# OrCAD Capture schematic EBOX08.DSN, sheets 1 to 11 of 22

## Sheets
1 22 A10-IO: size C
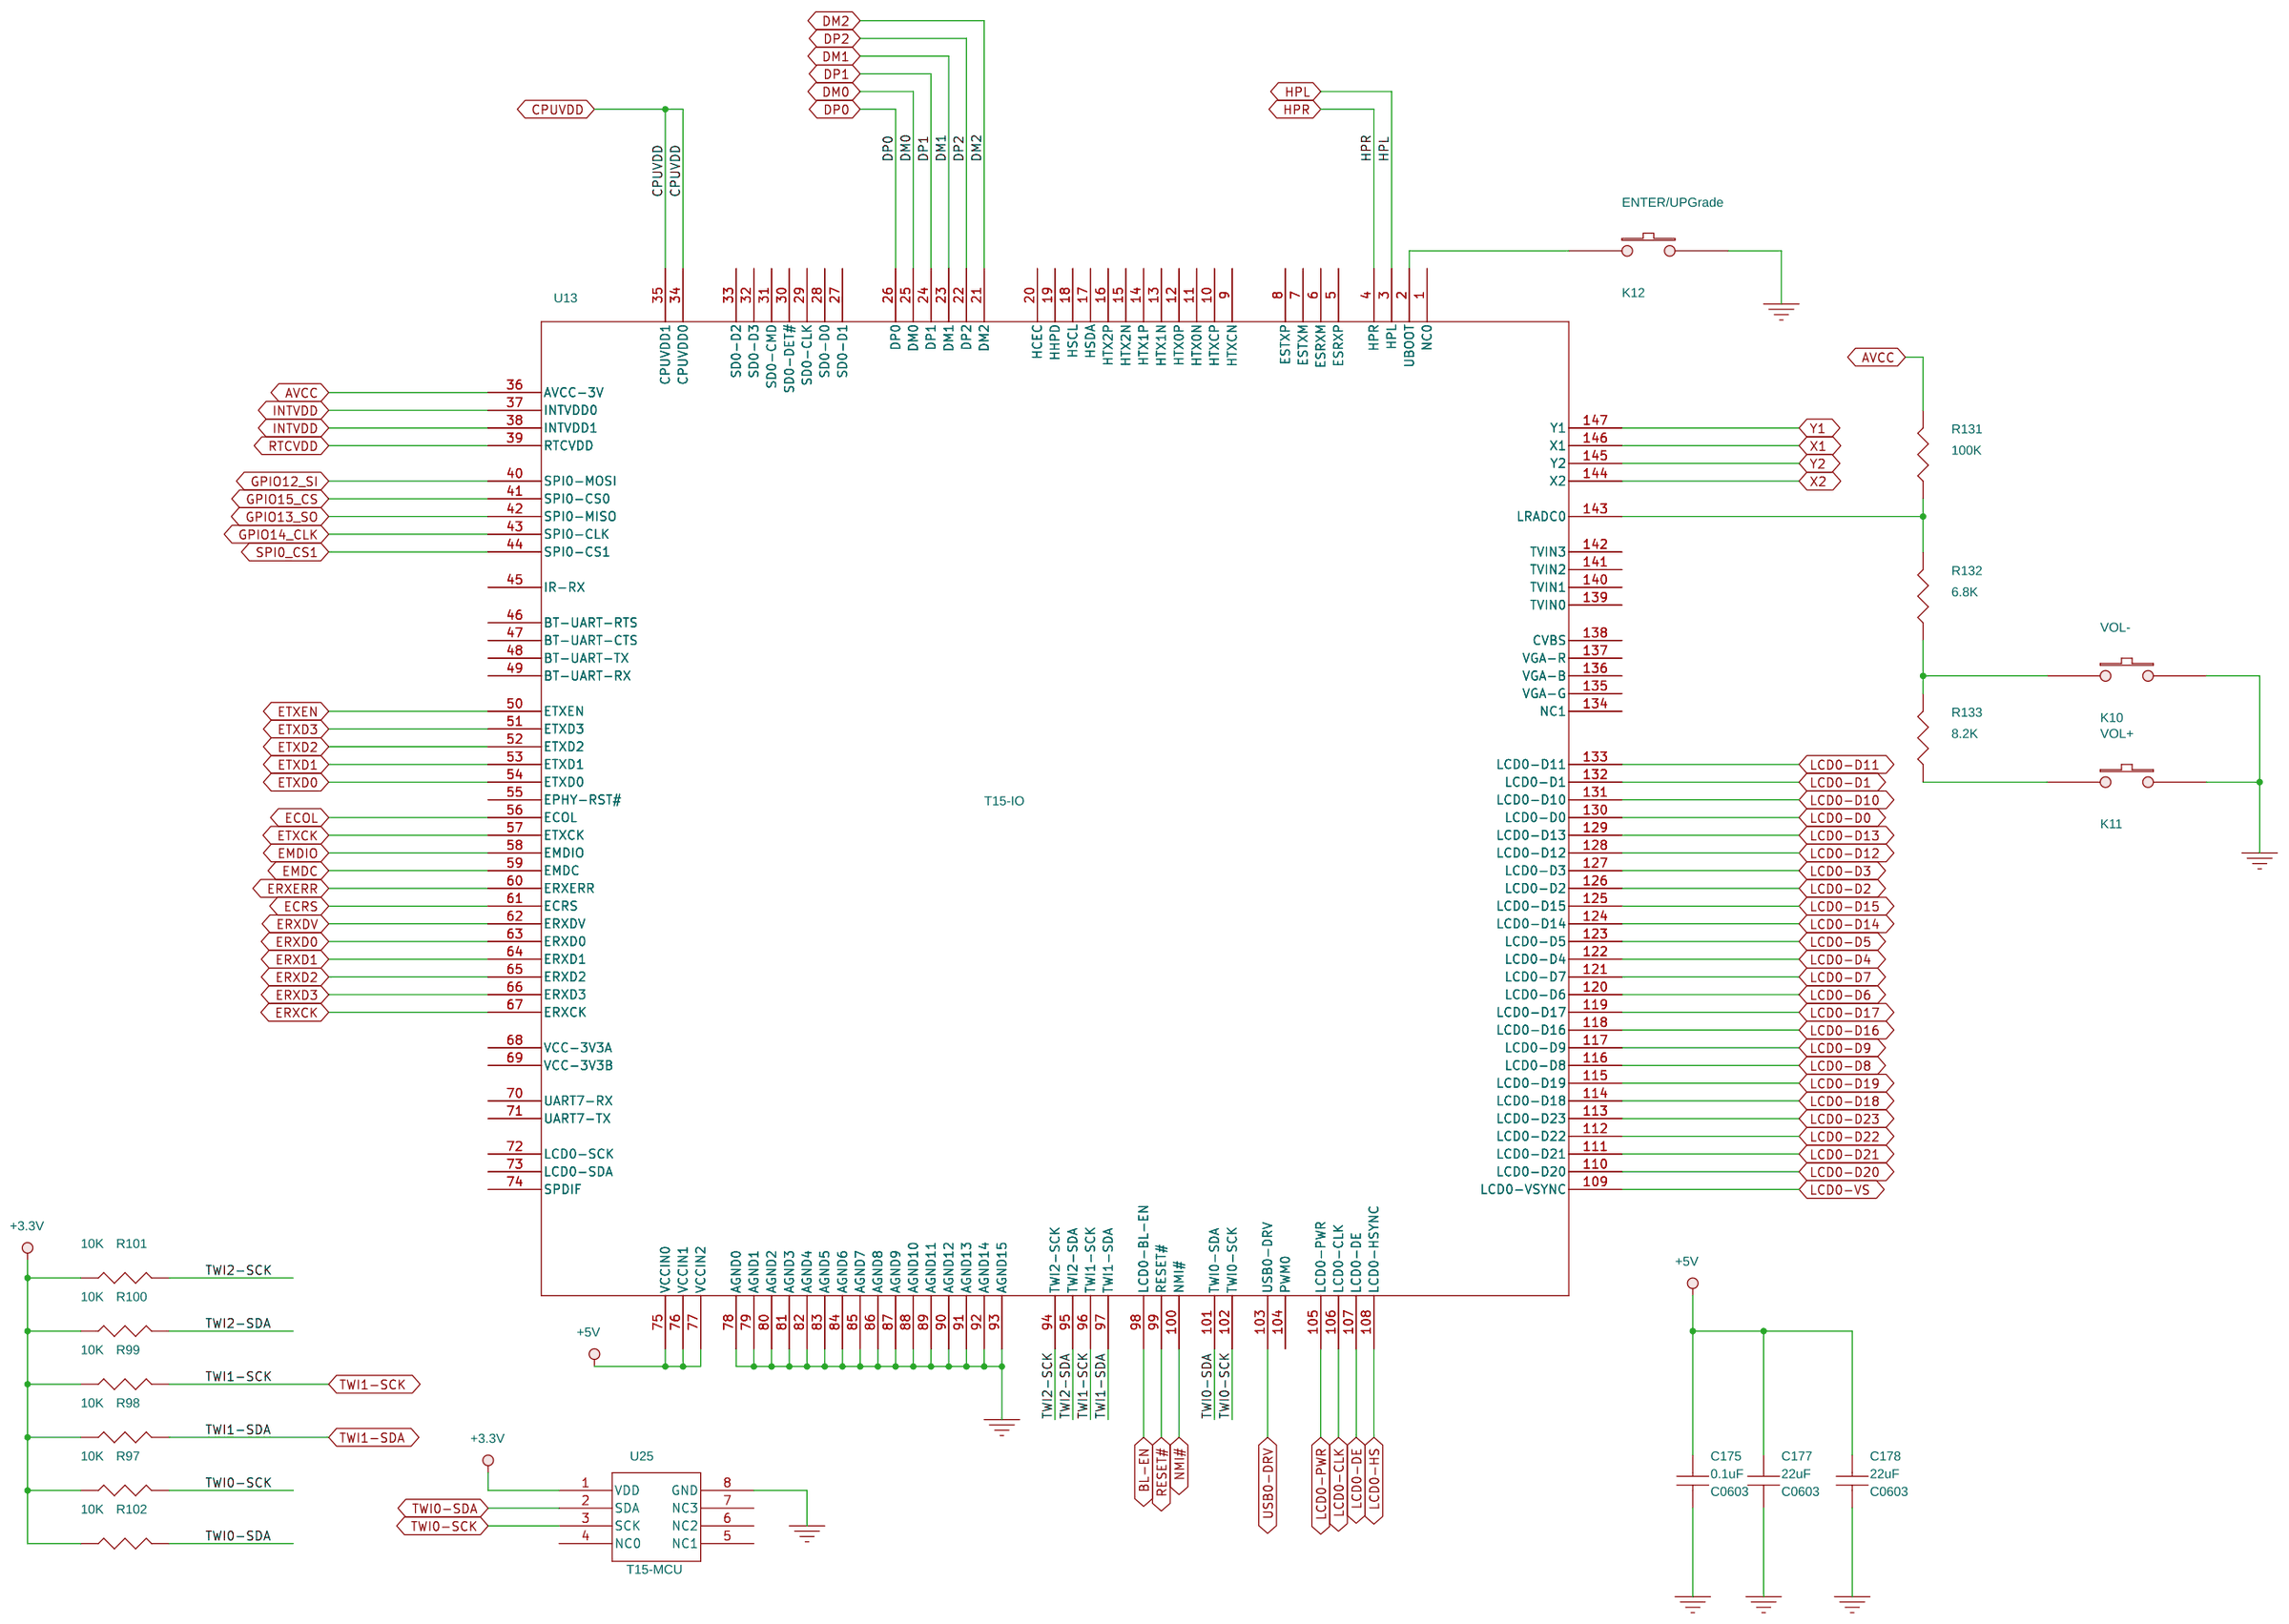
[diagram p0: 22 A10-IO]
2 01 BLOCK
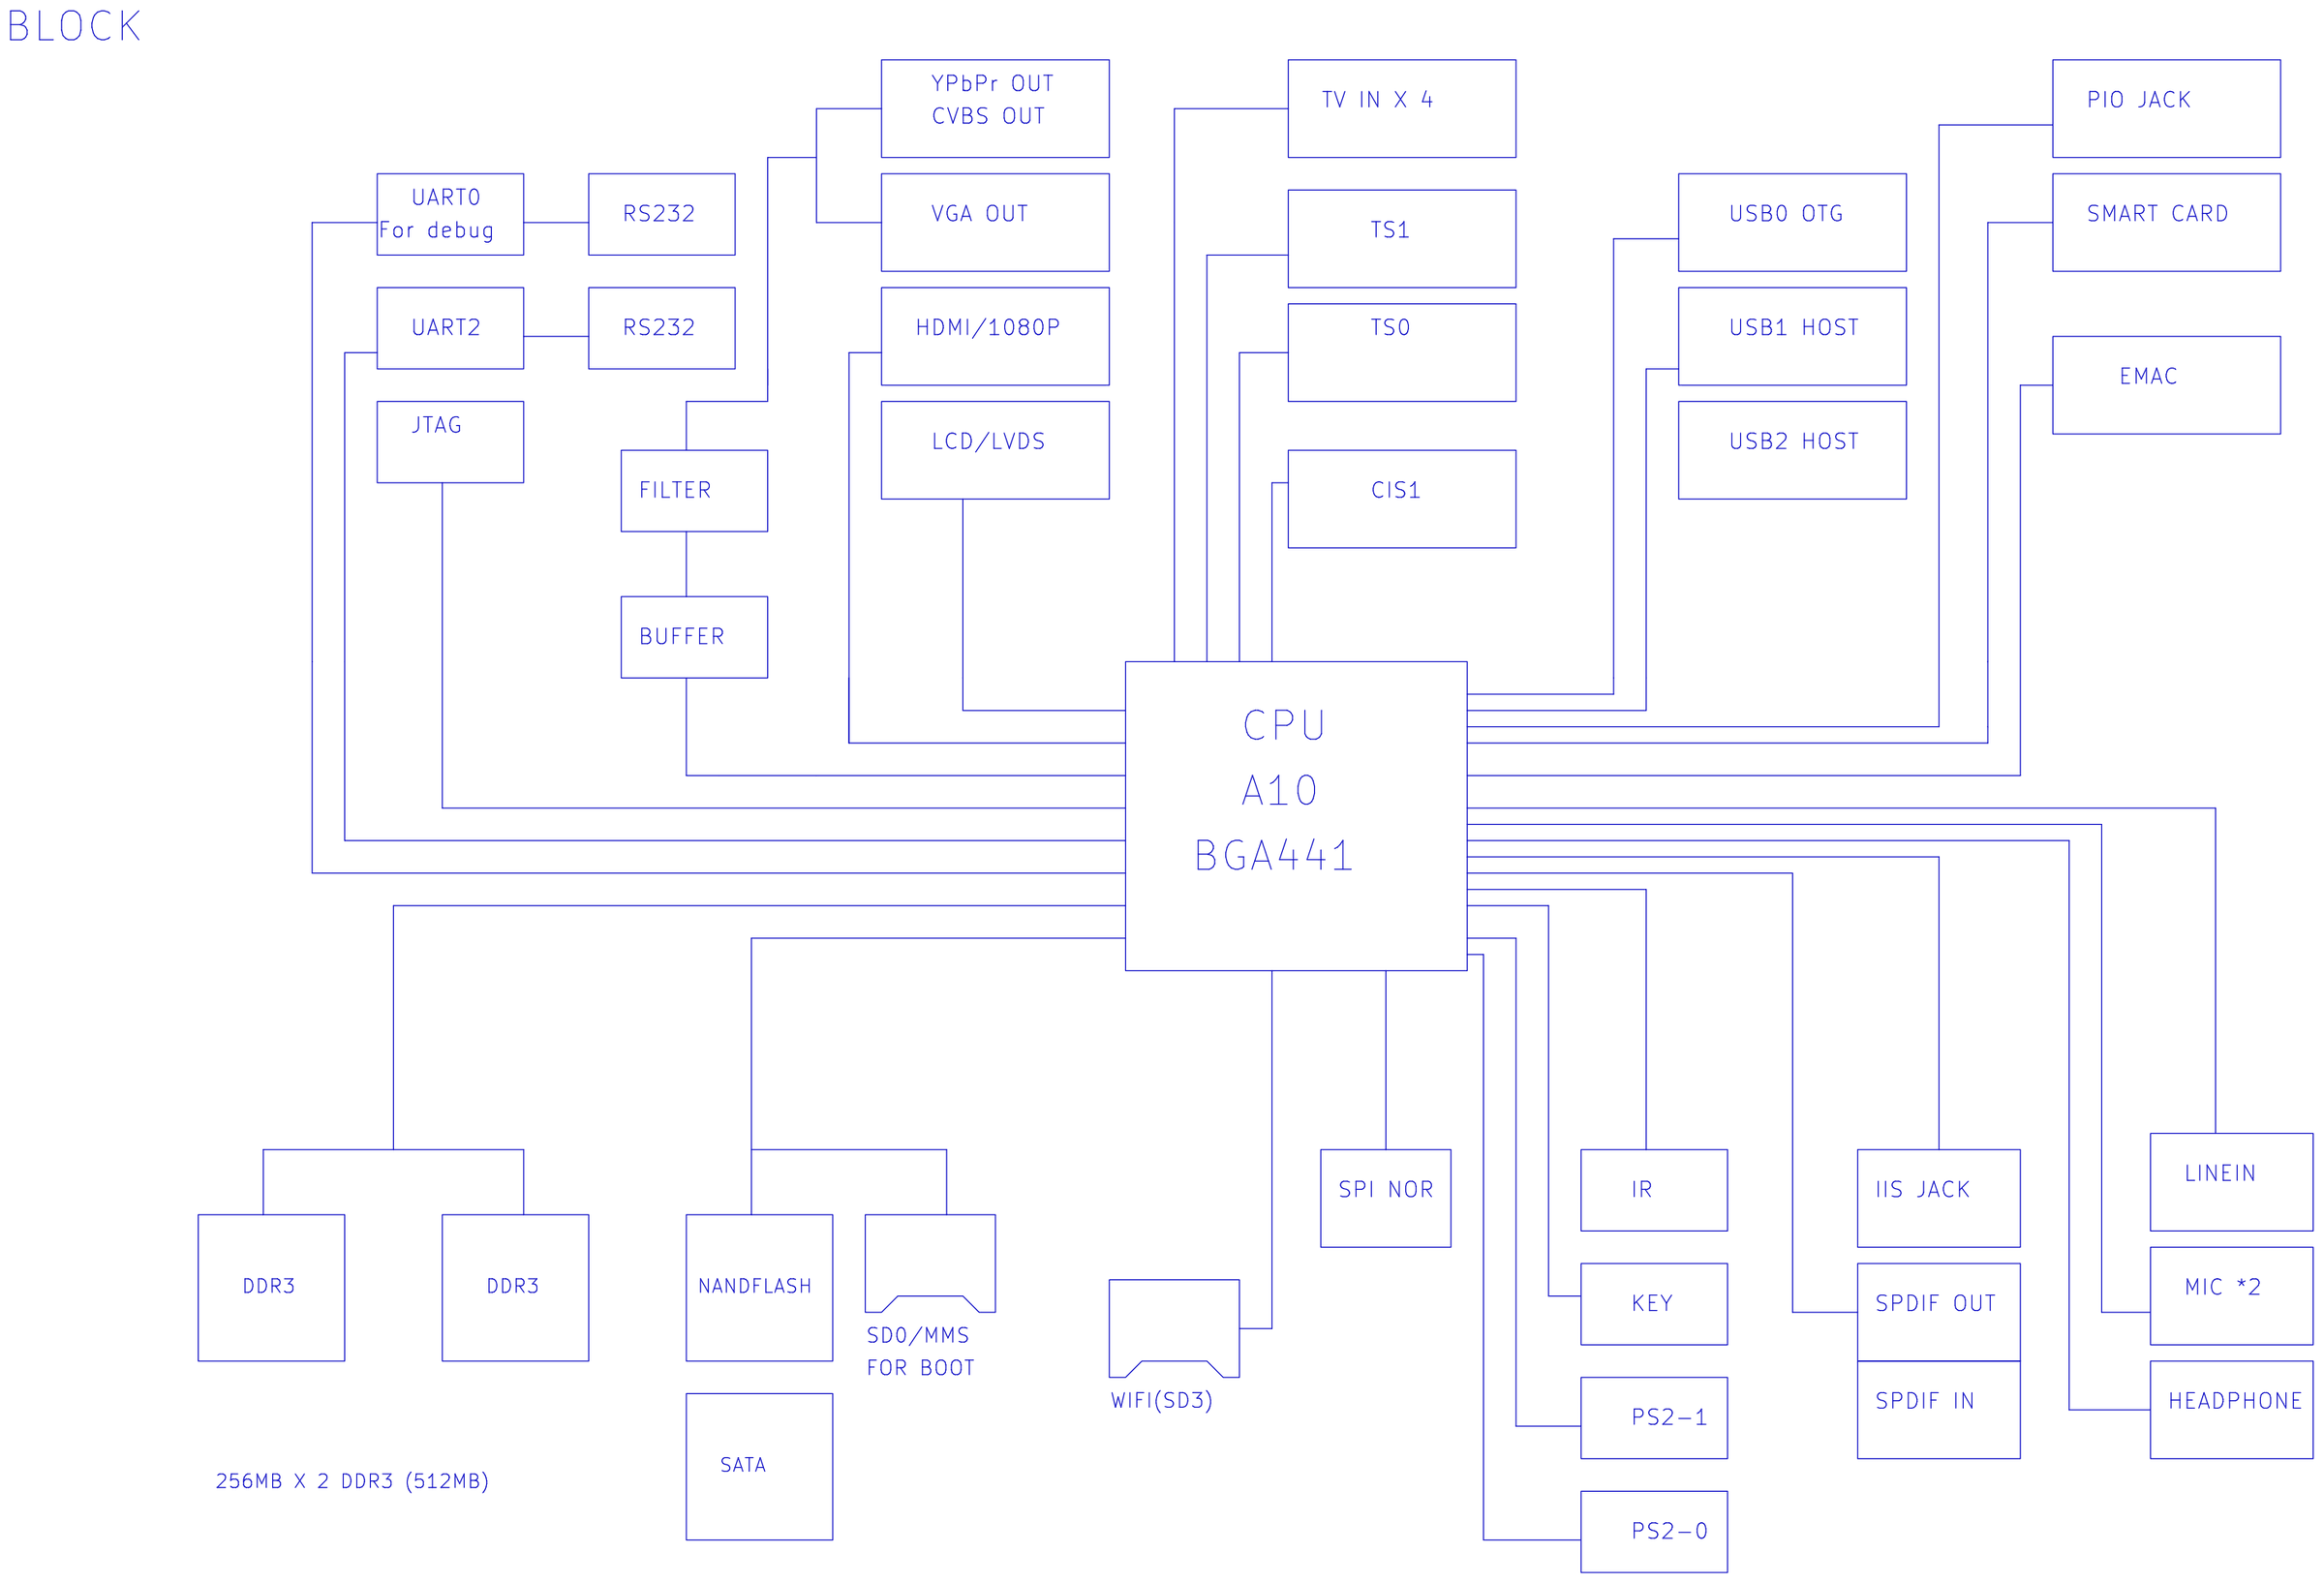
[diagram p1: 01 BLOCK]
3 02 PIO ASSIGNMENT
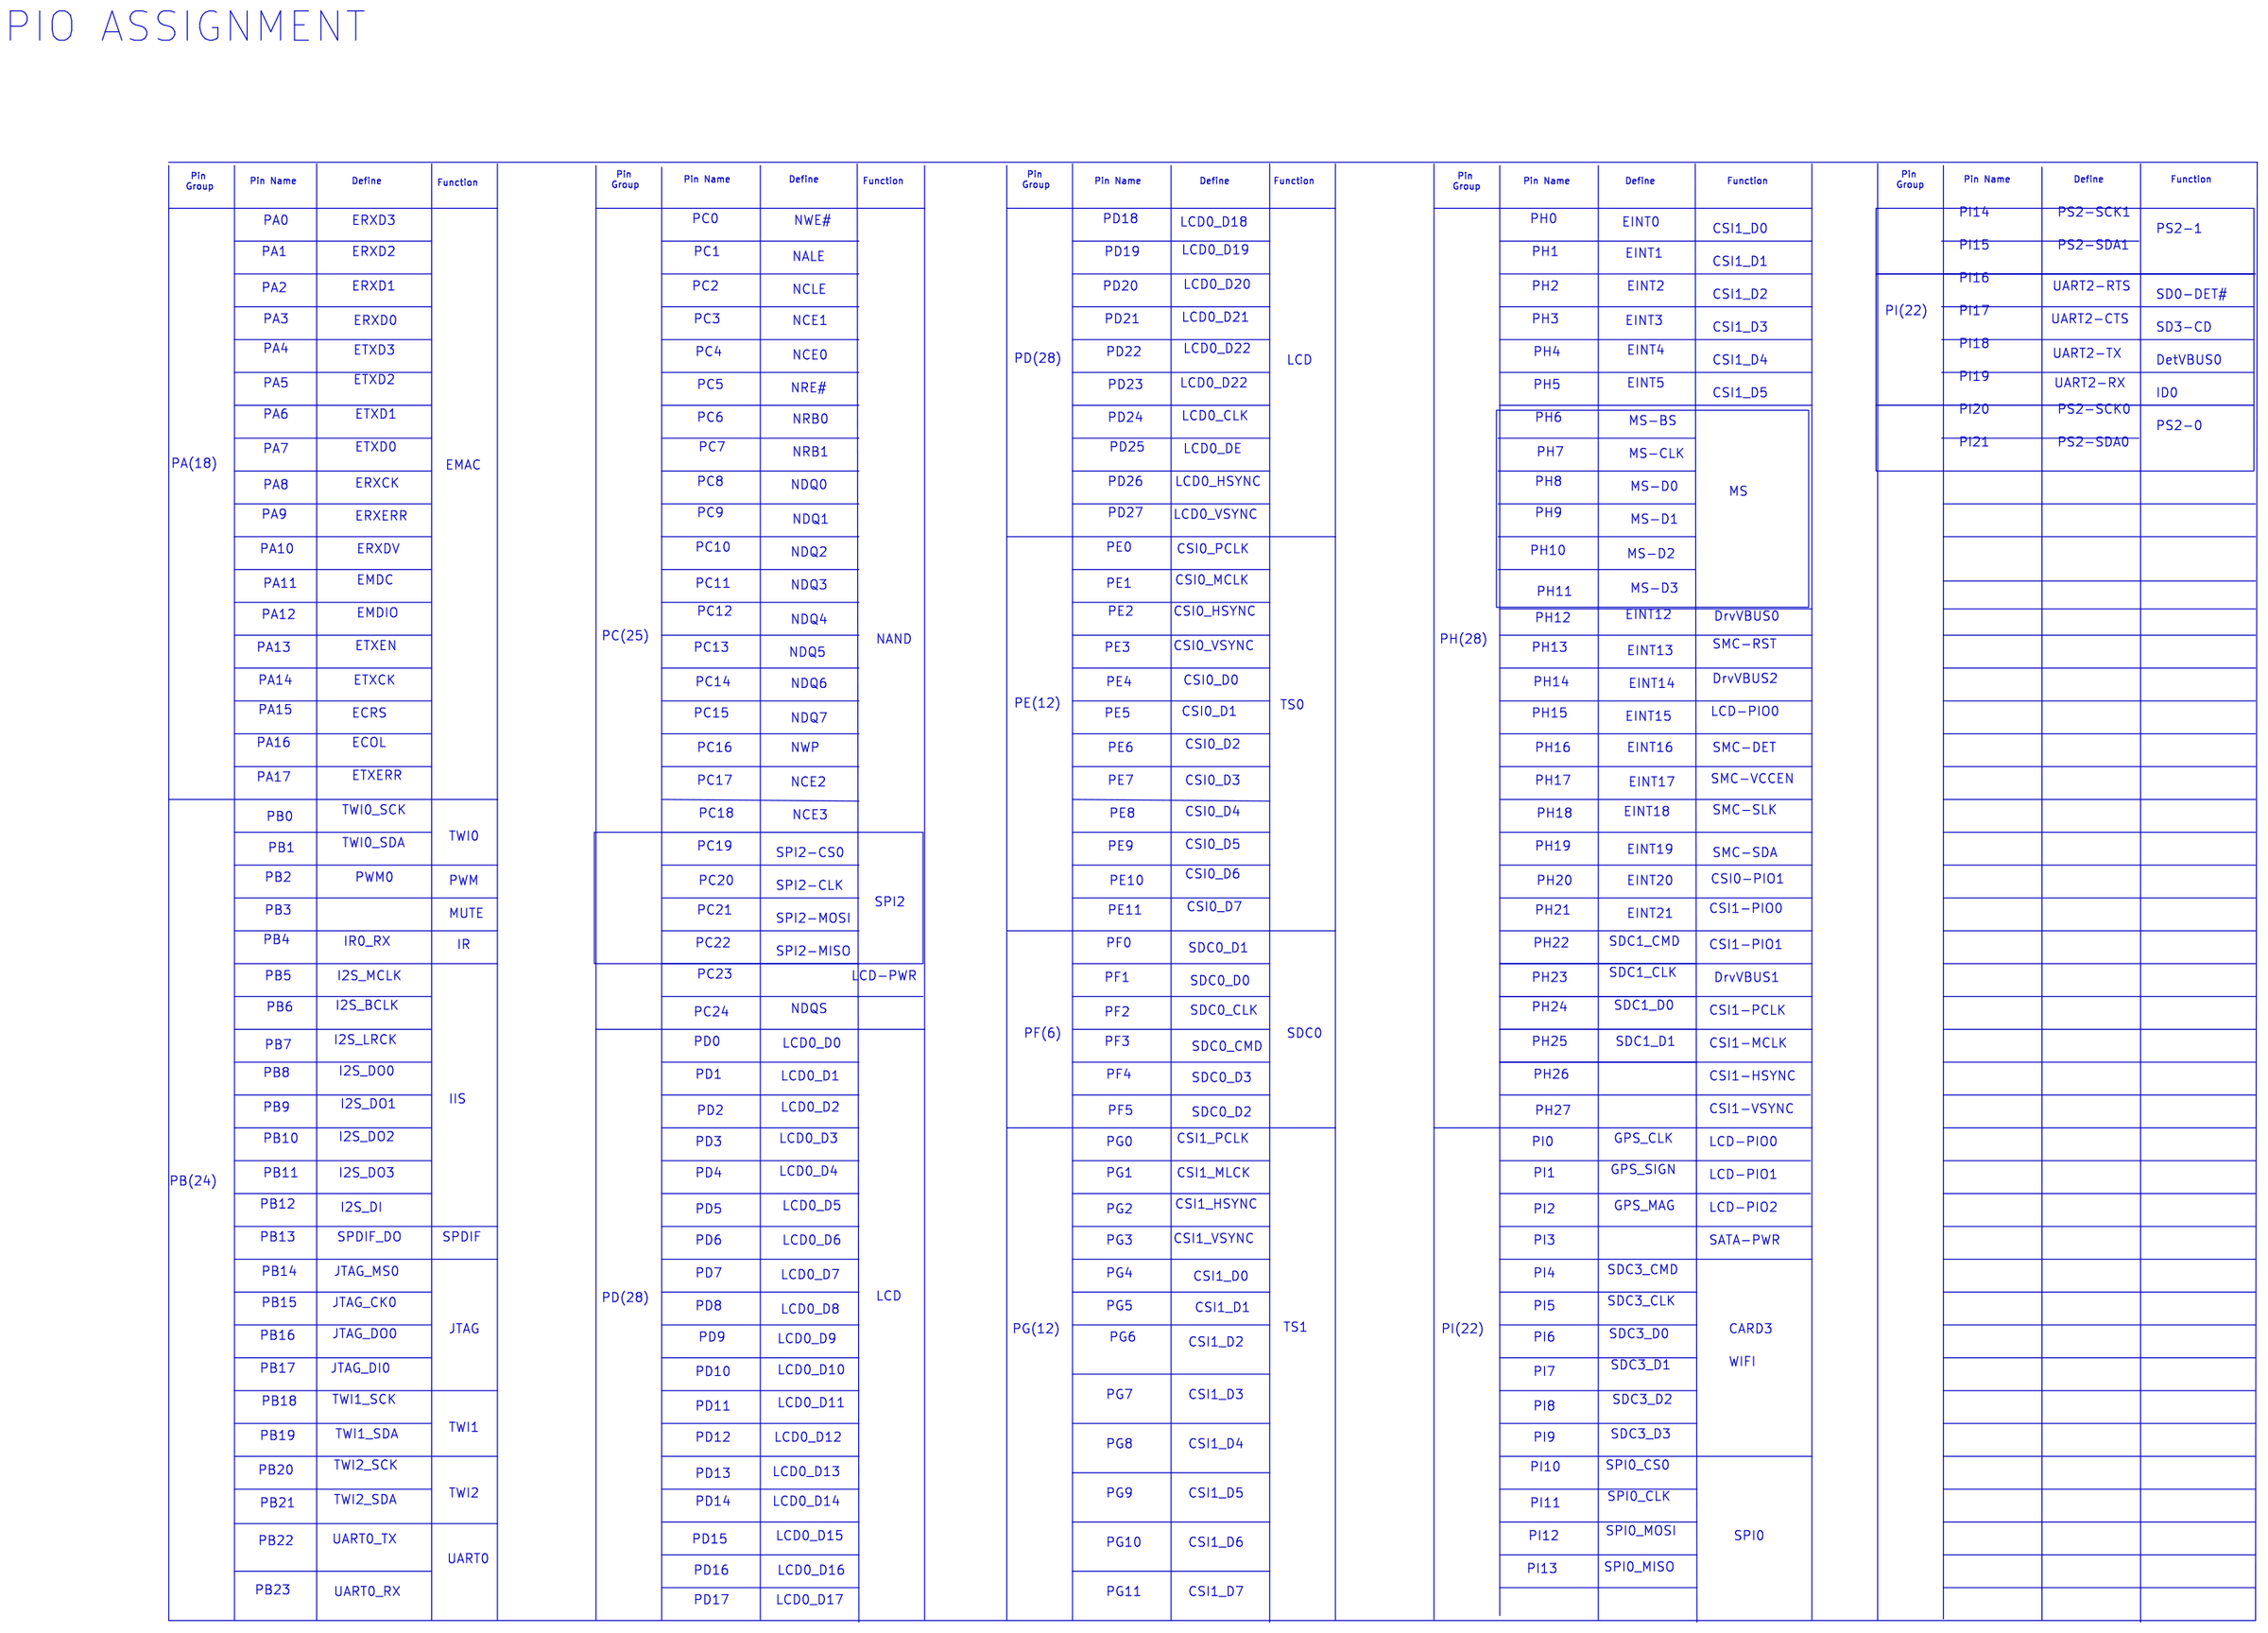
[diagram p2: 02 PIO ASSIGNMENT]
4 03 POWER TREE: title: A10-EVB-TVD-V10; rev: 1.0; note: POWER TREE
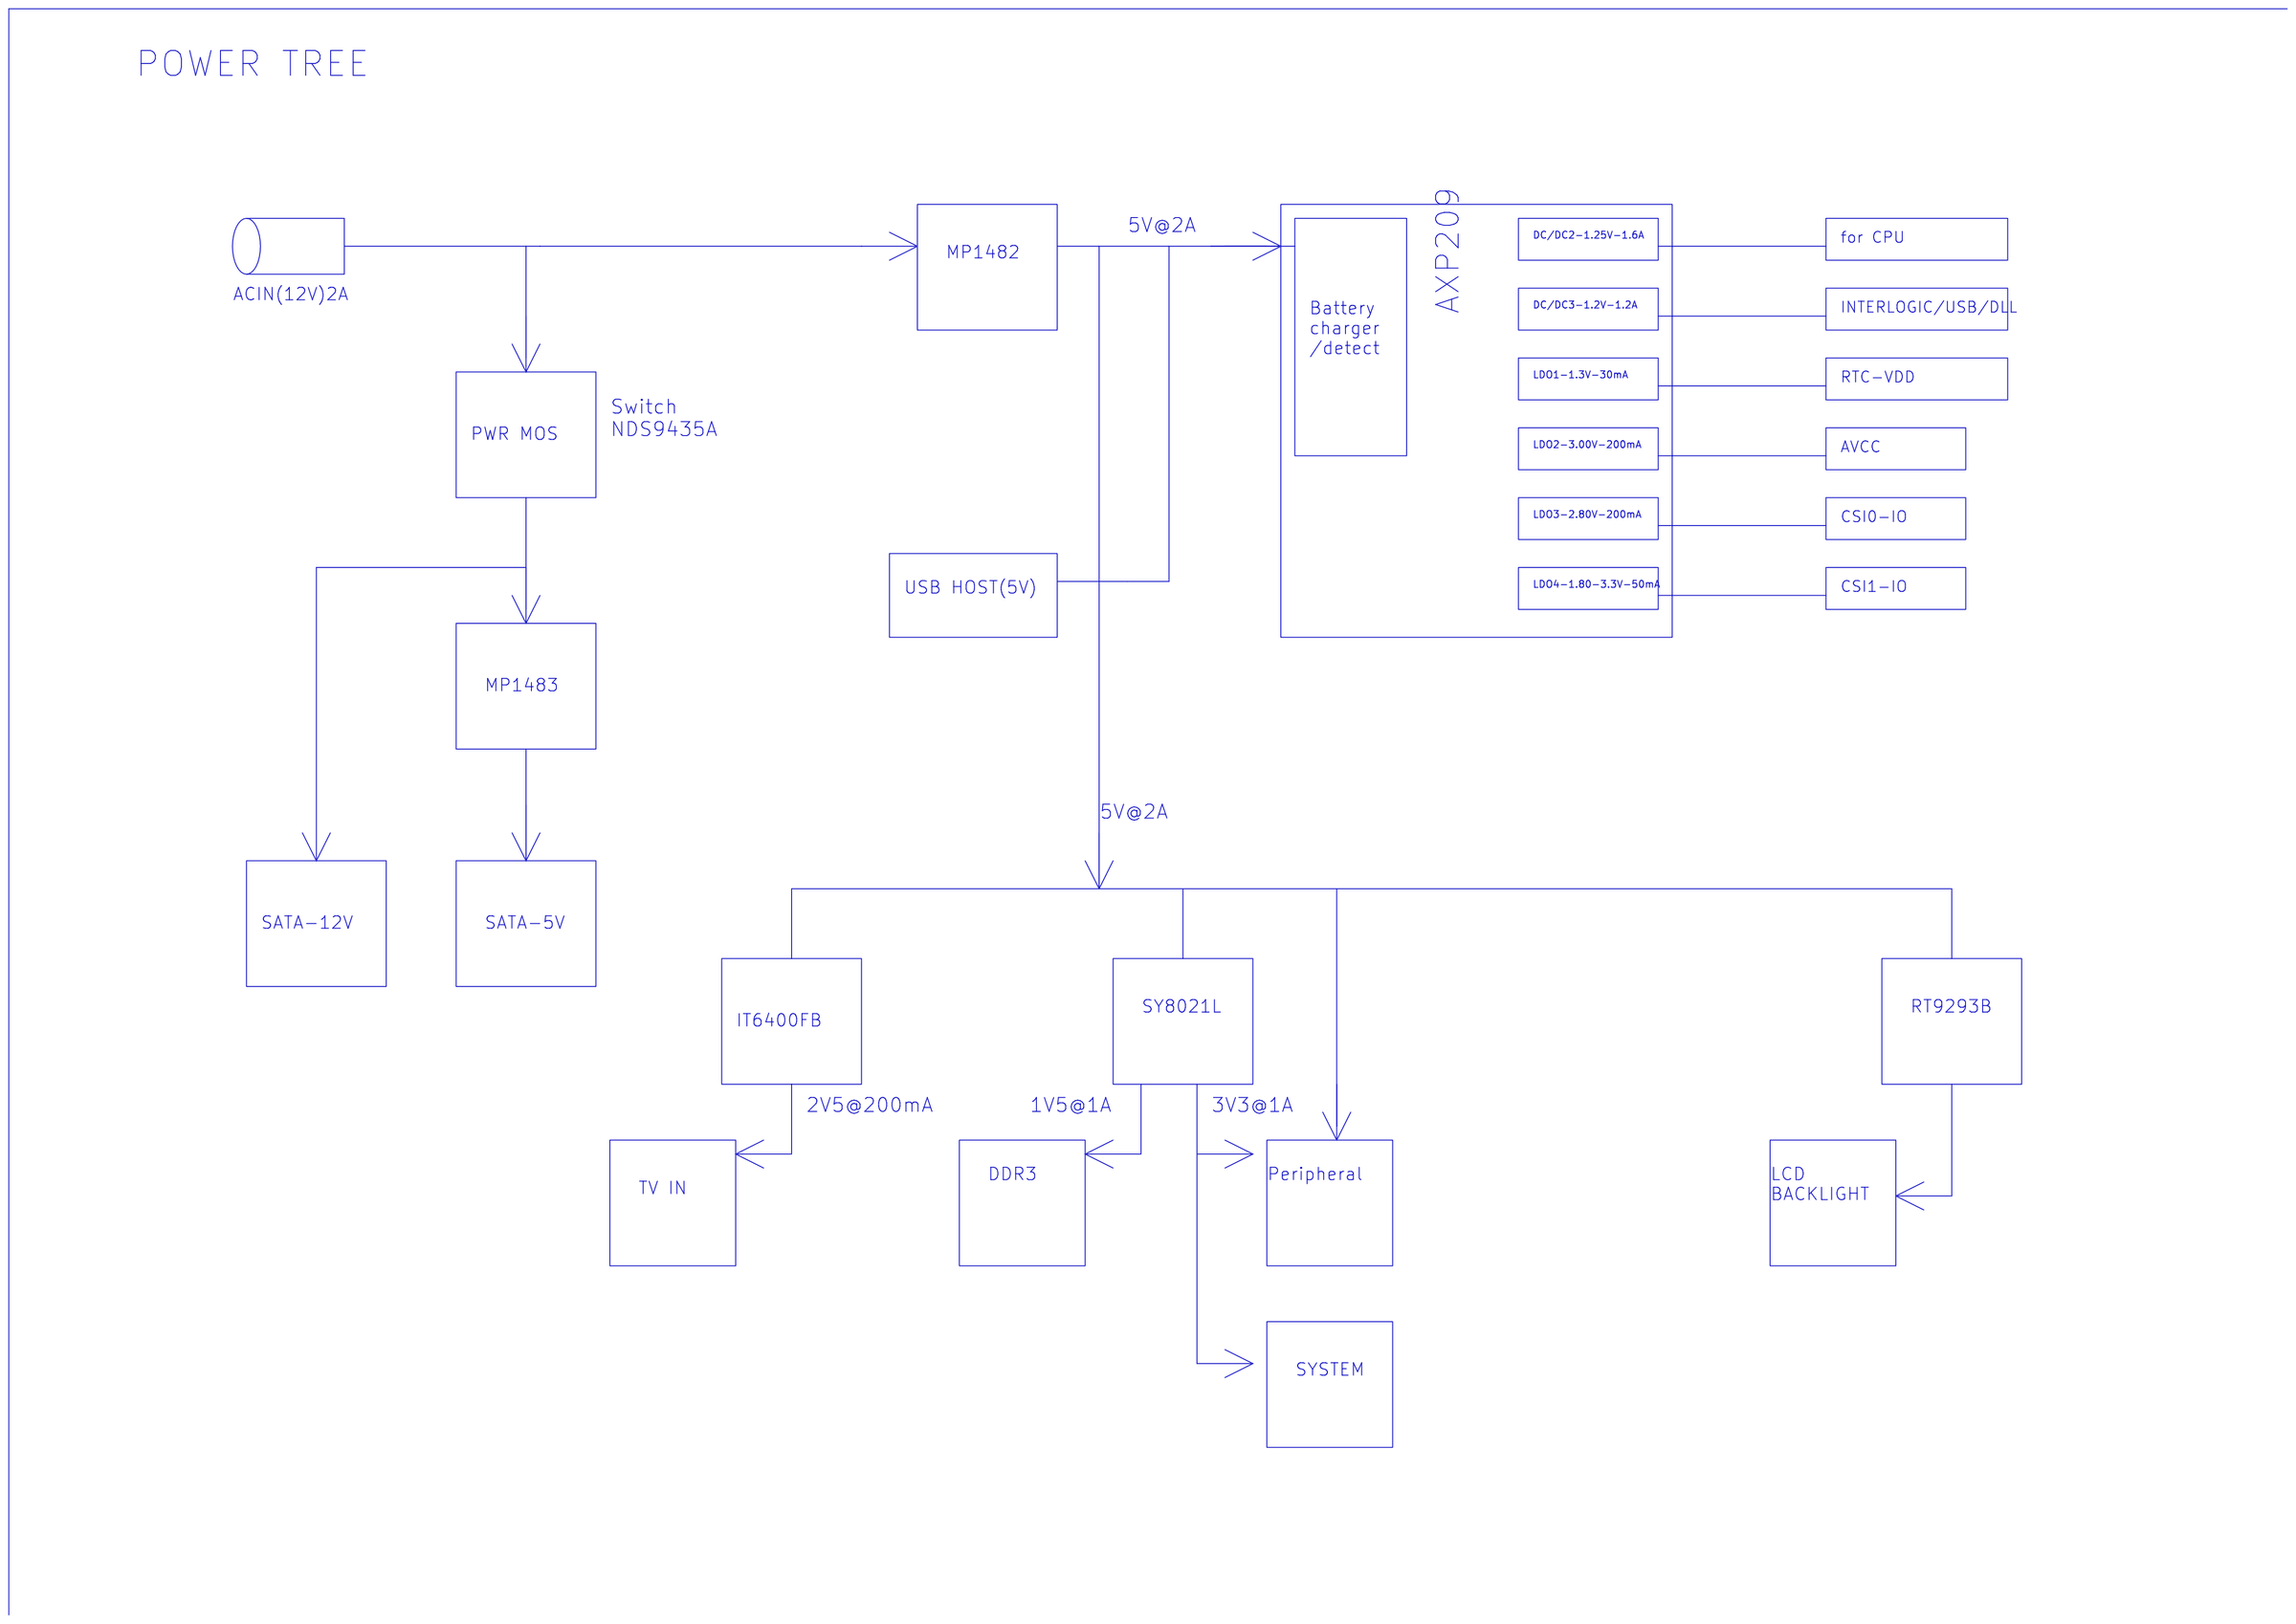
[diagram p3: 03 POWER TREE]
5 04 CPU1: size A3; title: A10-EVB-TVD-V10; rev: 1.0; note: CPU1
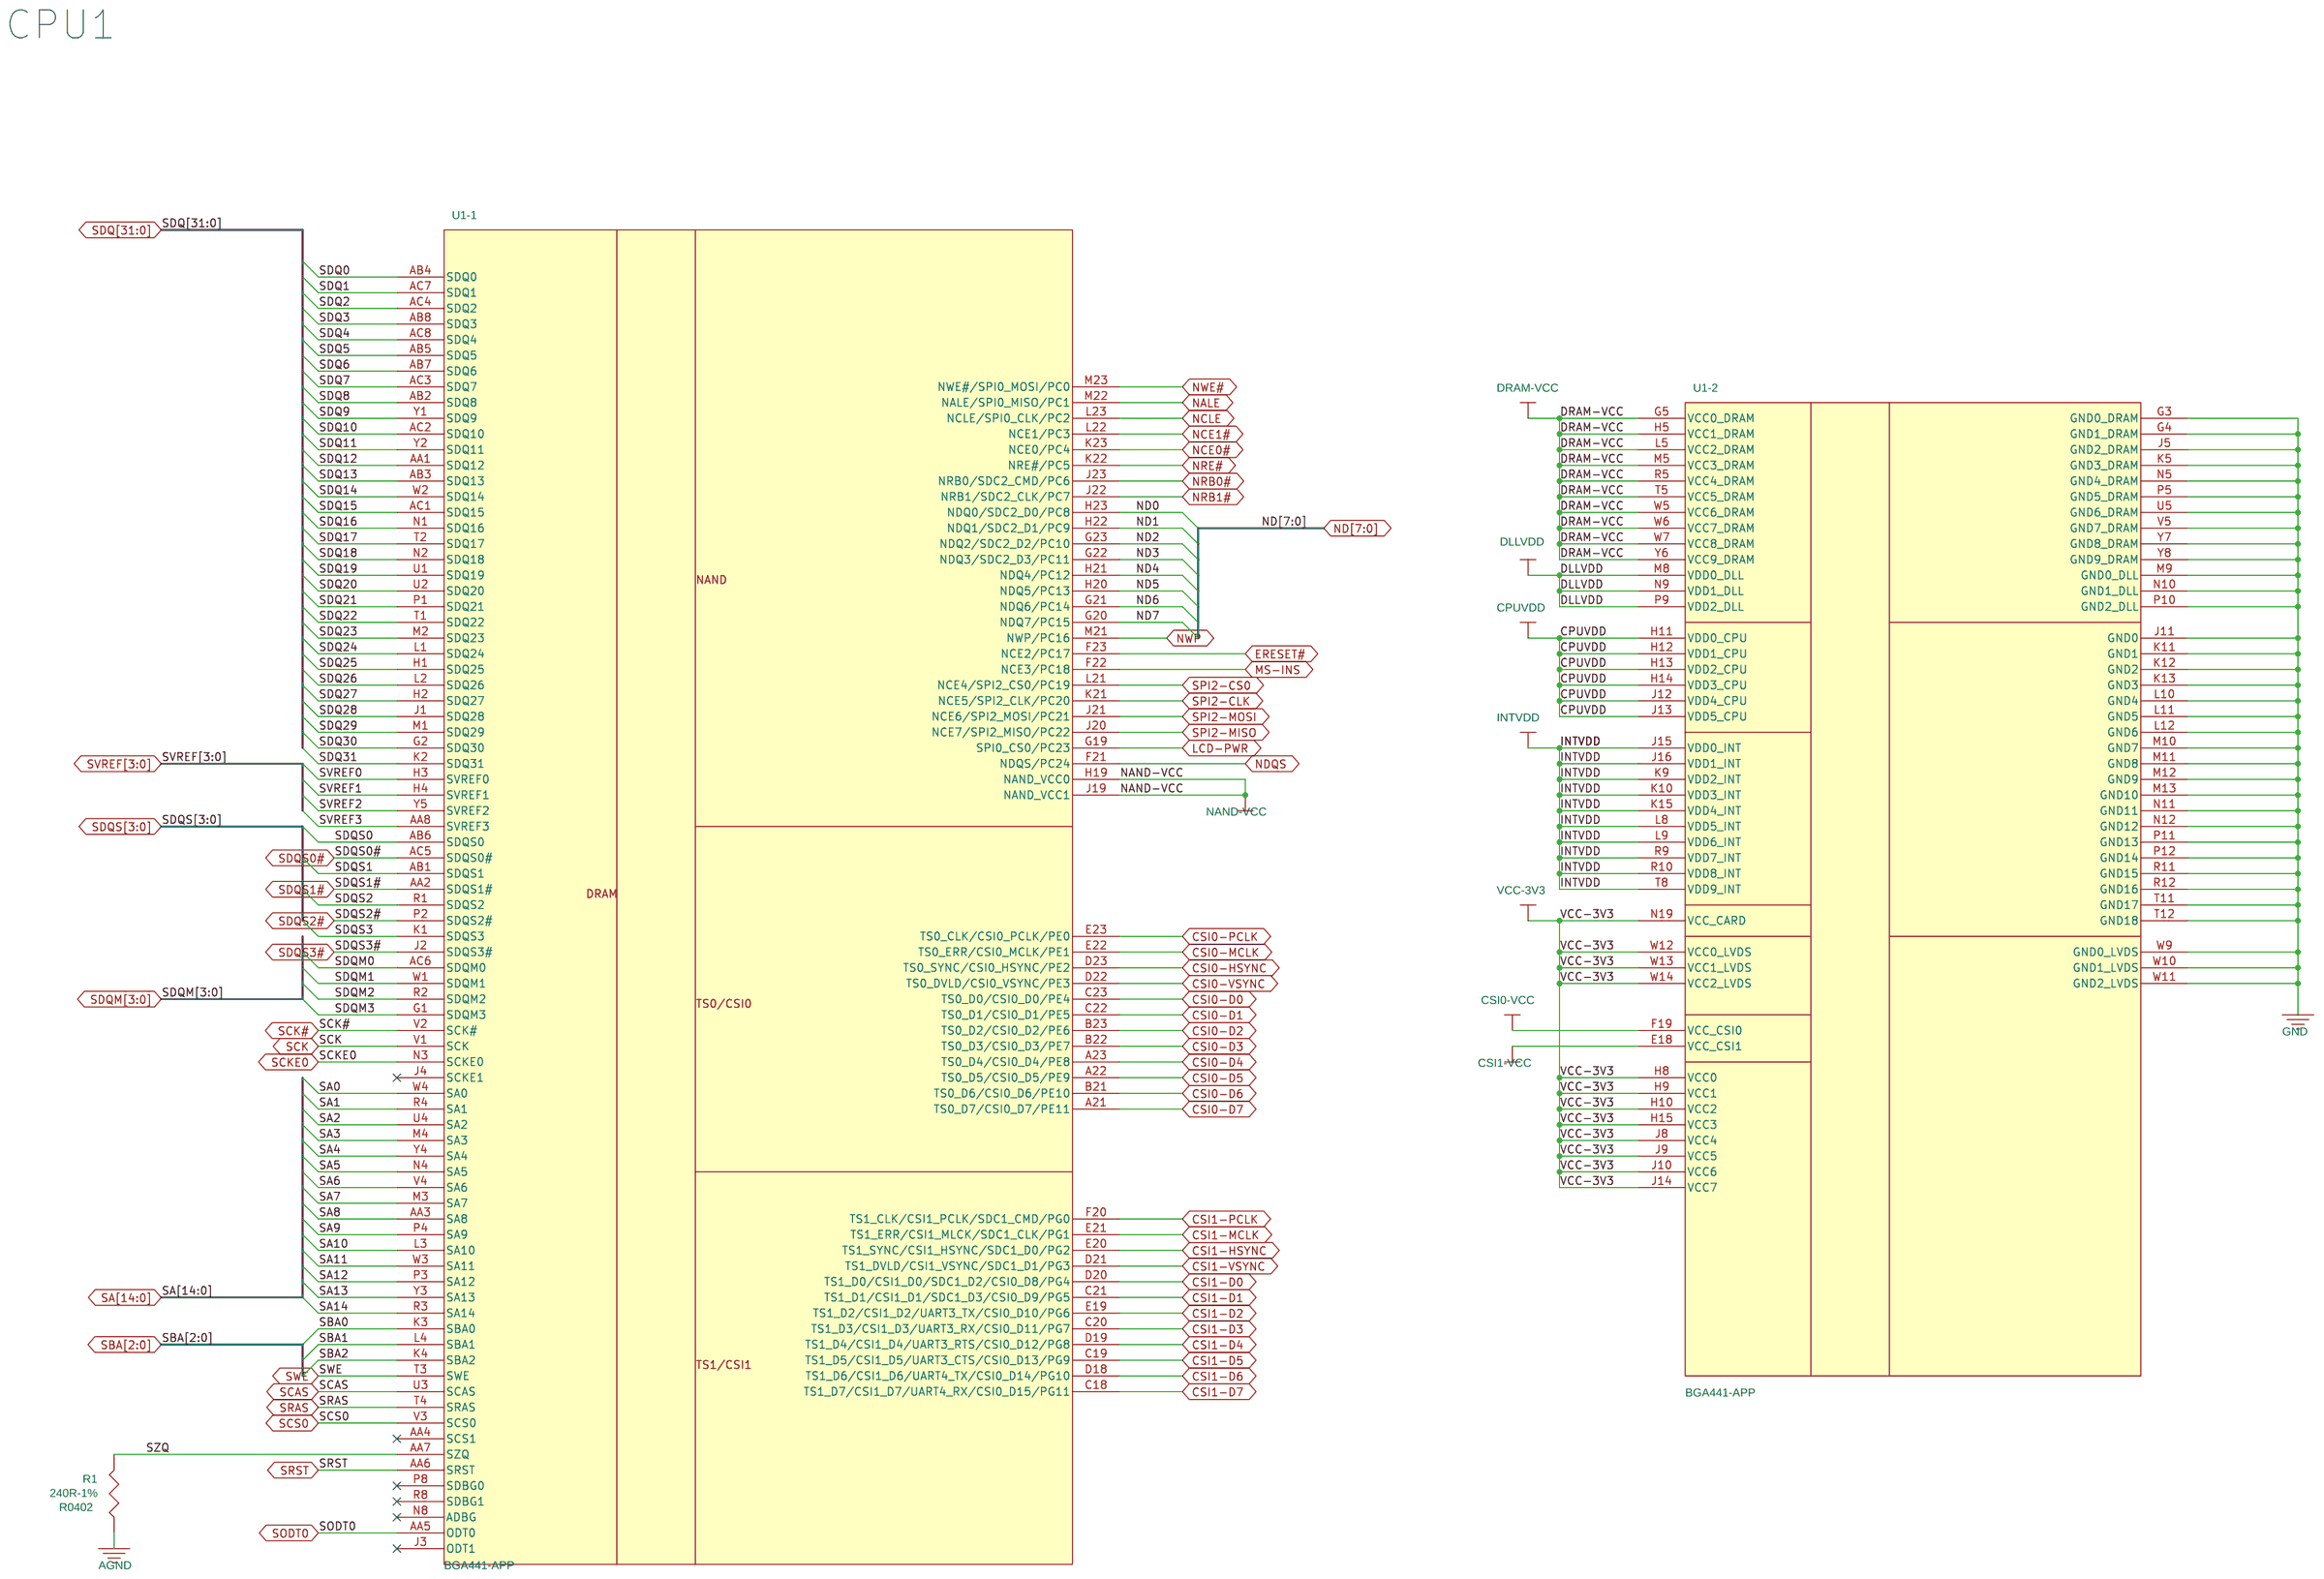
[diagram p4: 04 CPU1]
6 05 CPU2: size A3; title: A10-EVB-TVD-V10; rev: 1.0; note: CPU2
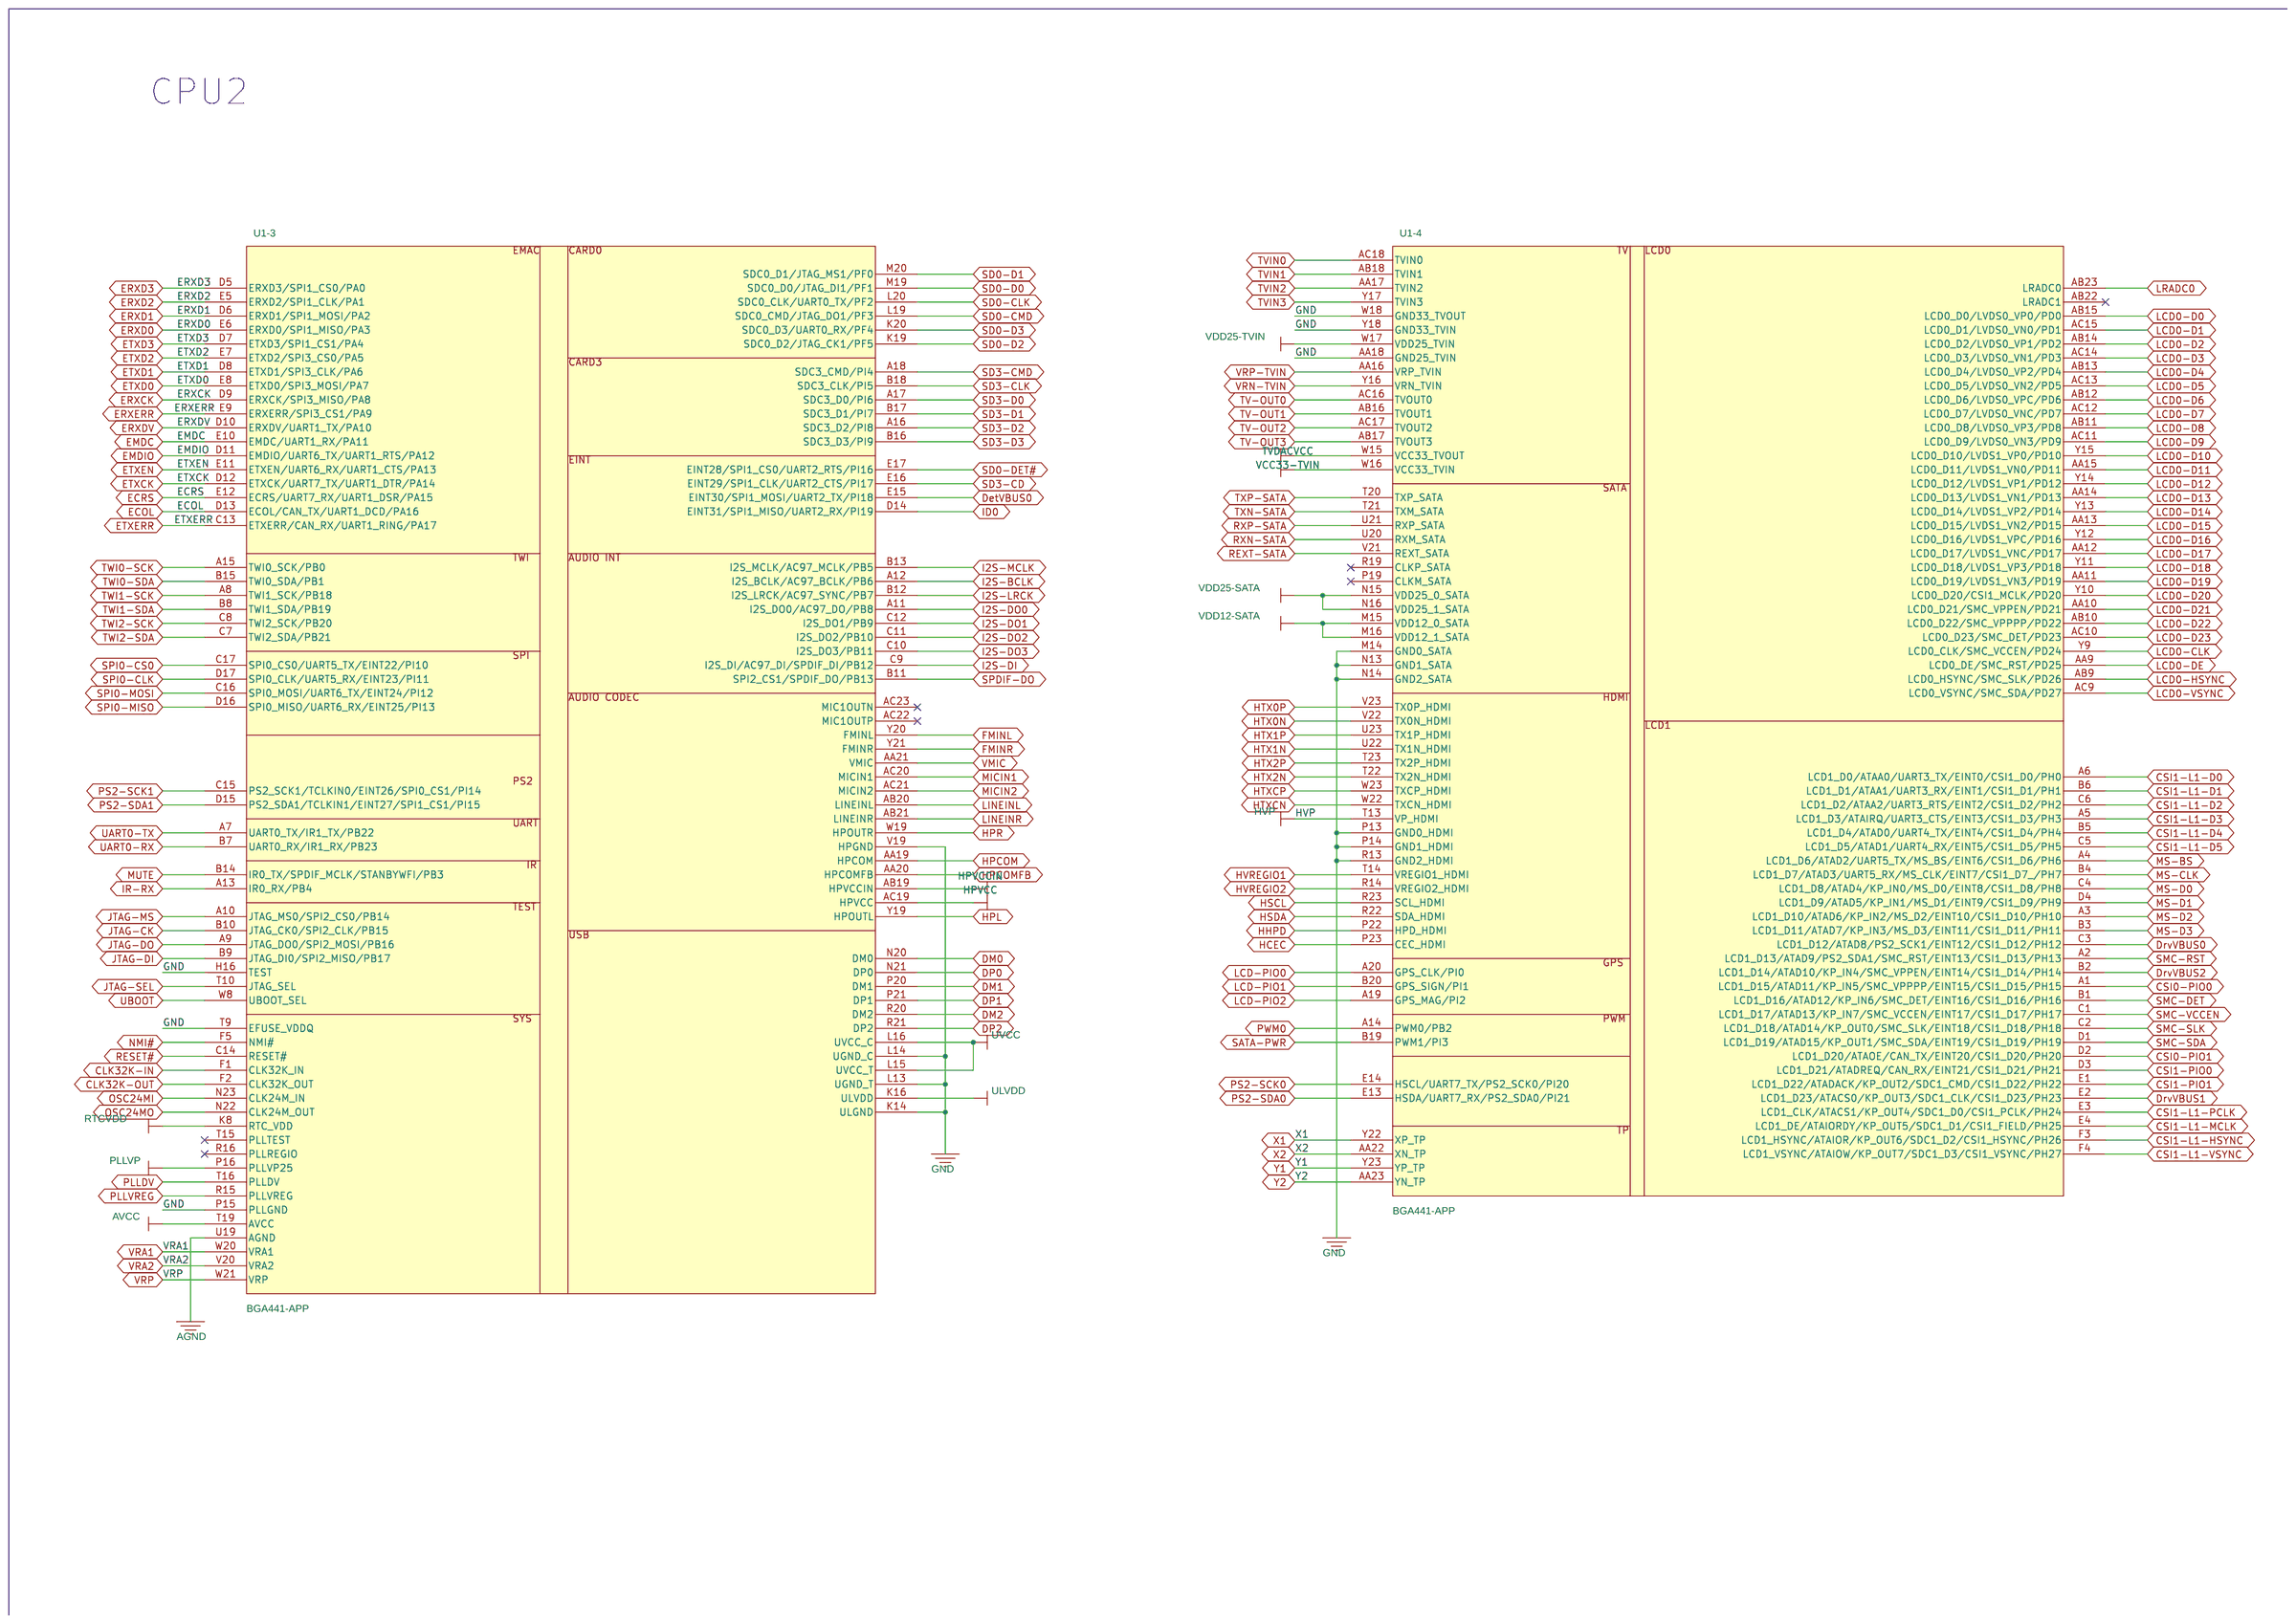
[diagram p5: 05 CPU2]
7 06 BESIDE CPU: size A3
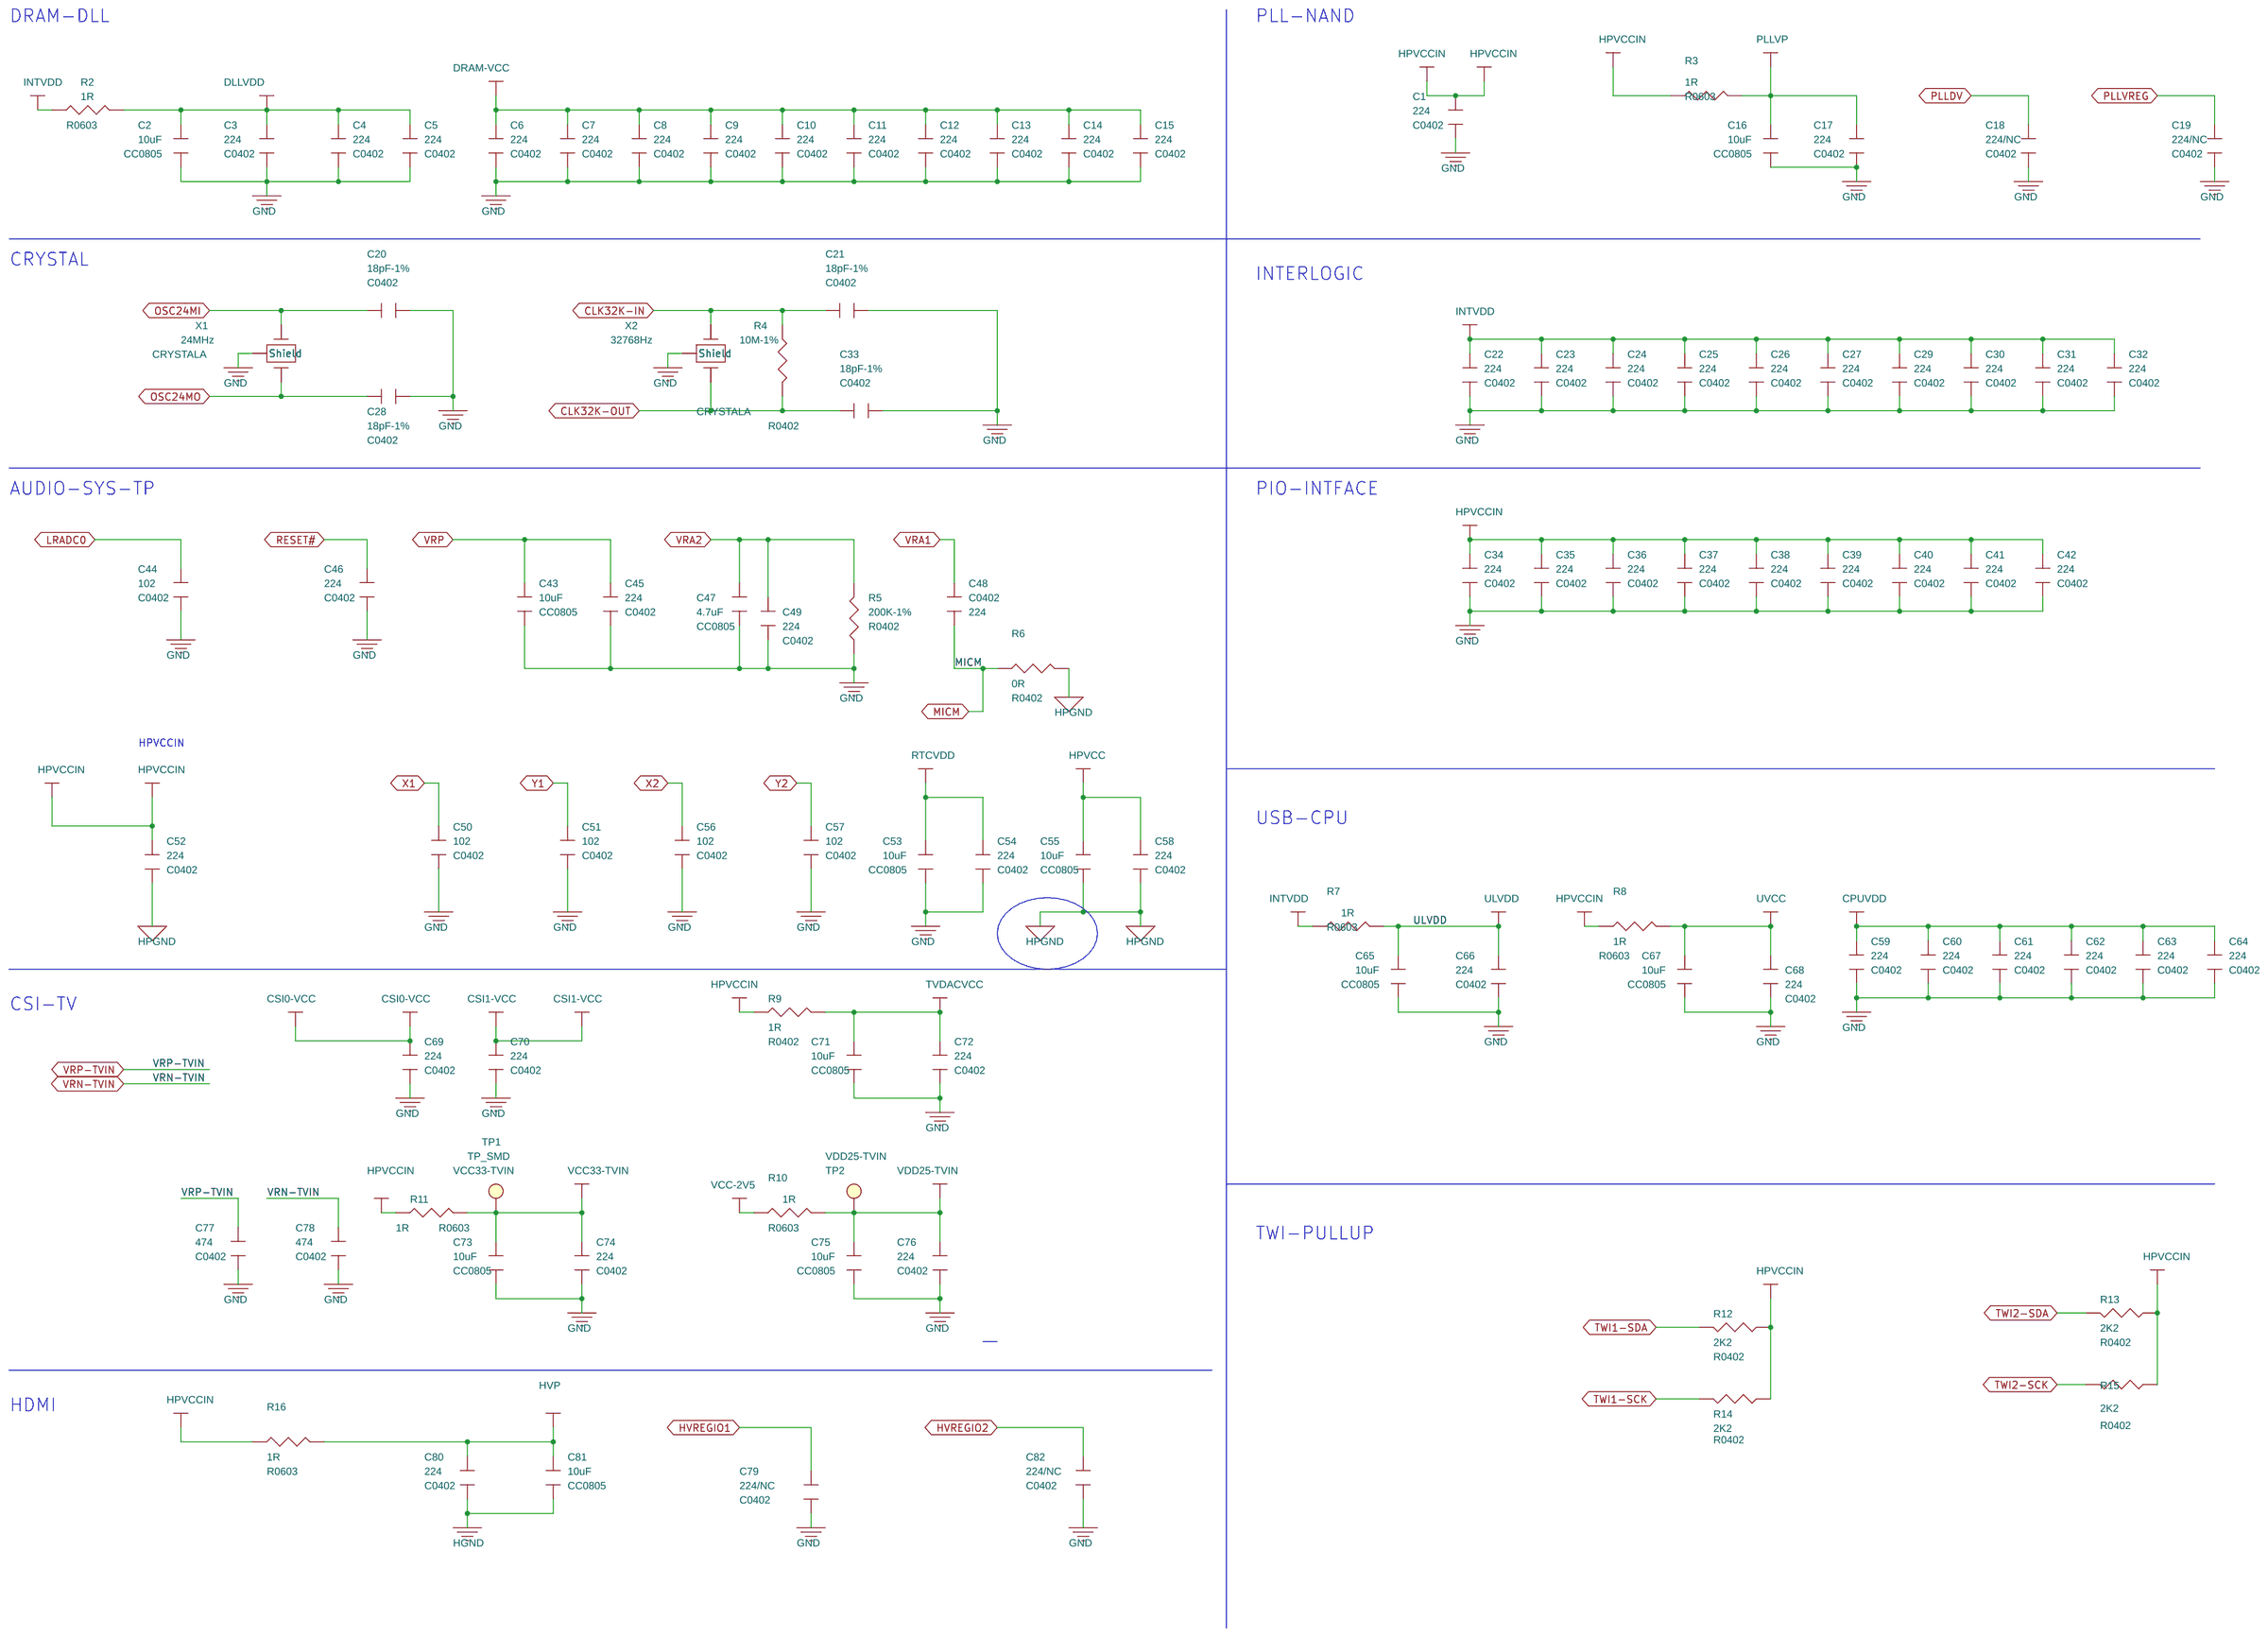
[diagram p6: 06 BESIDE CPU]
8 09 DRAM3: size A3
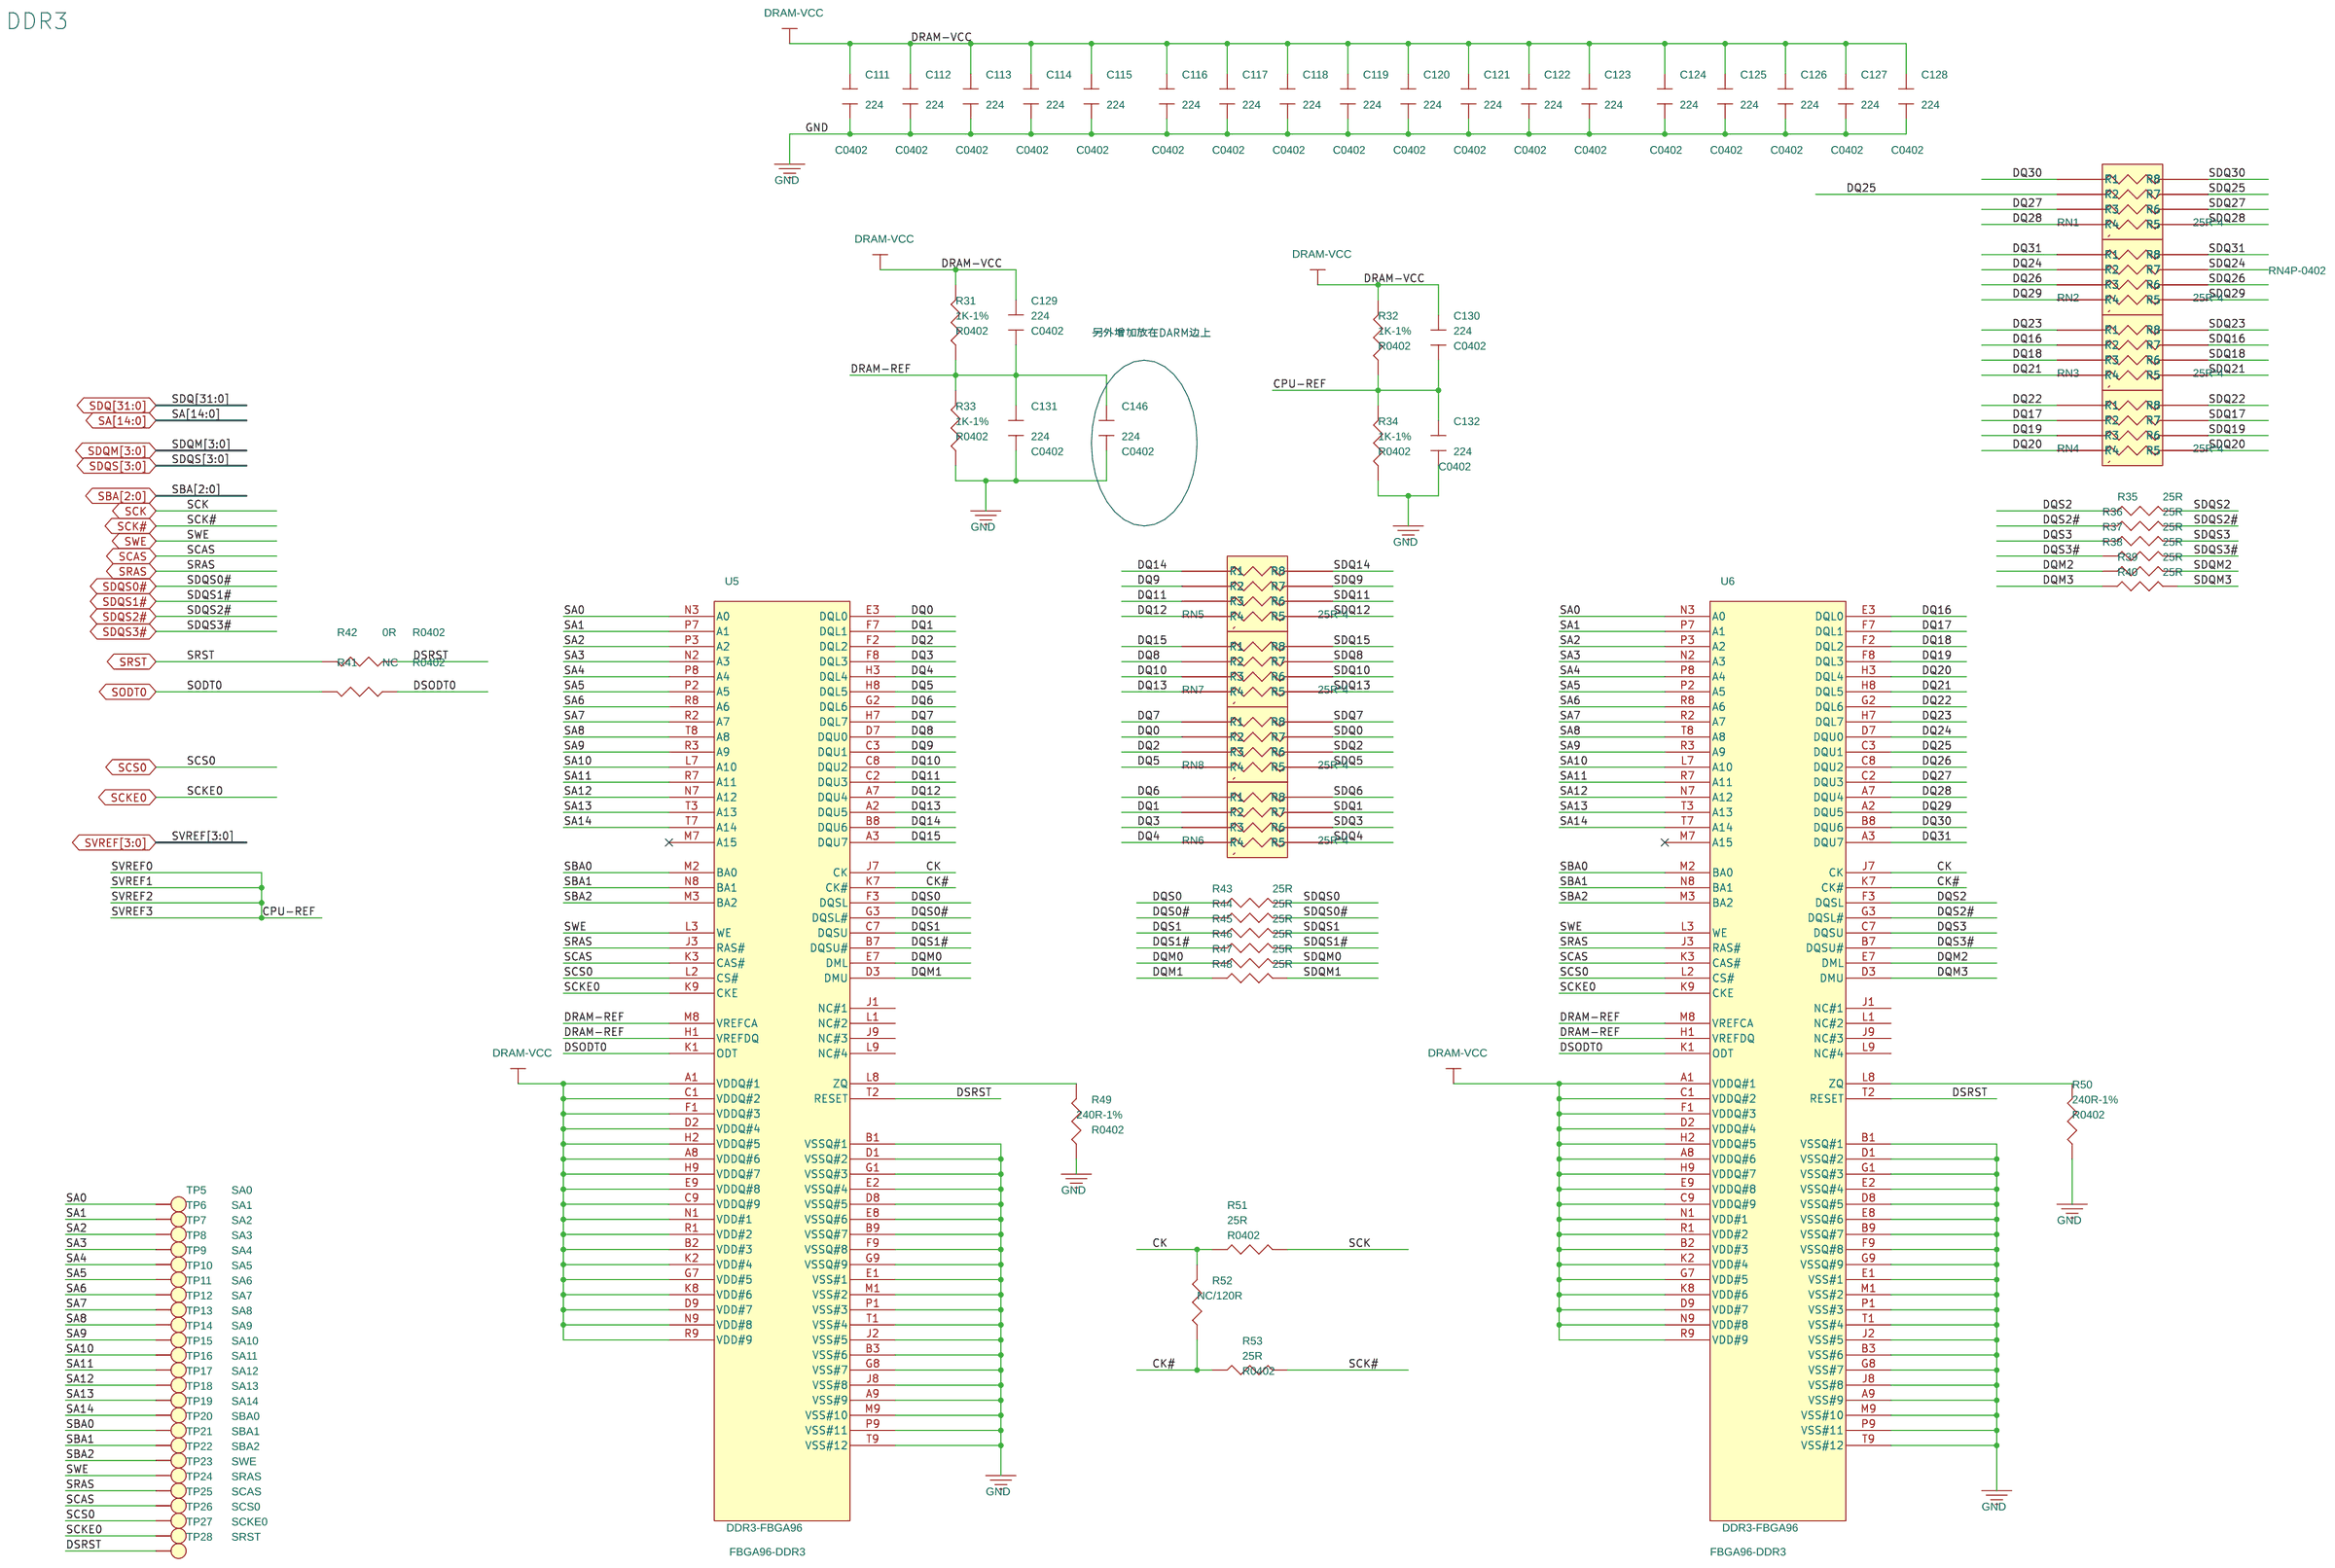
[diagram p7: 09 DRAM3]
9 10 NC: size A3
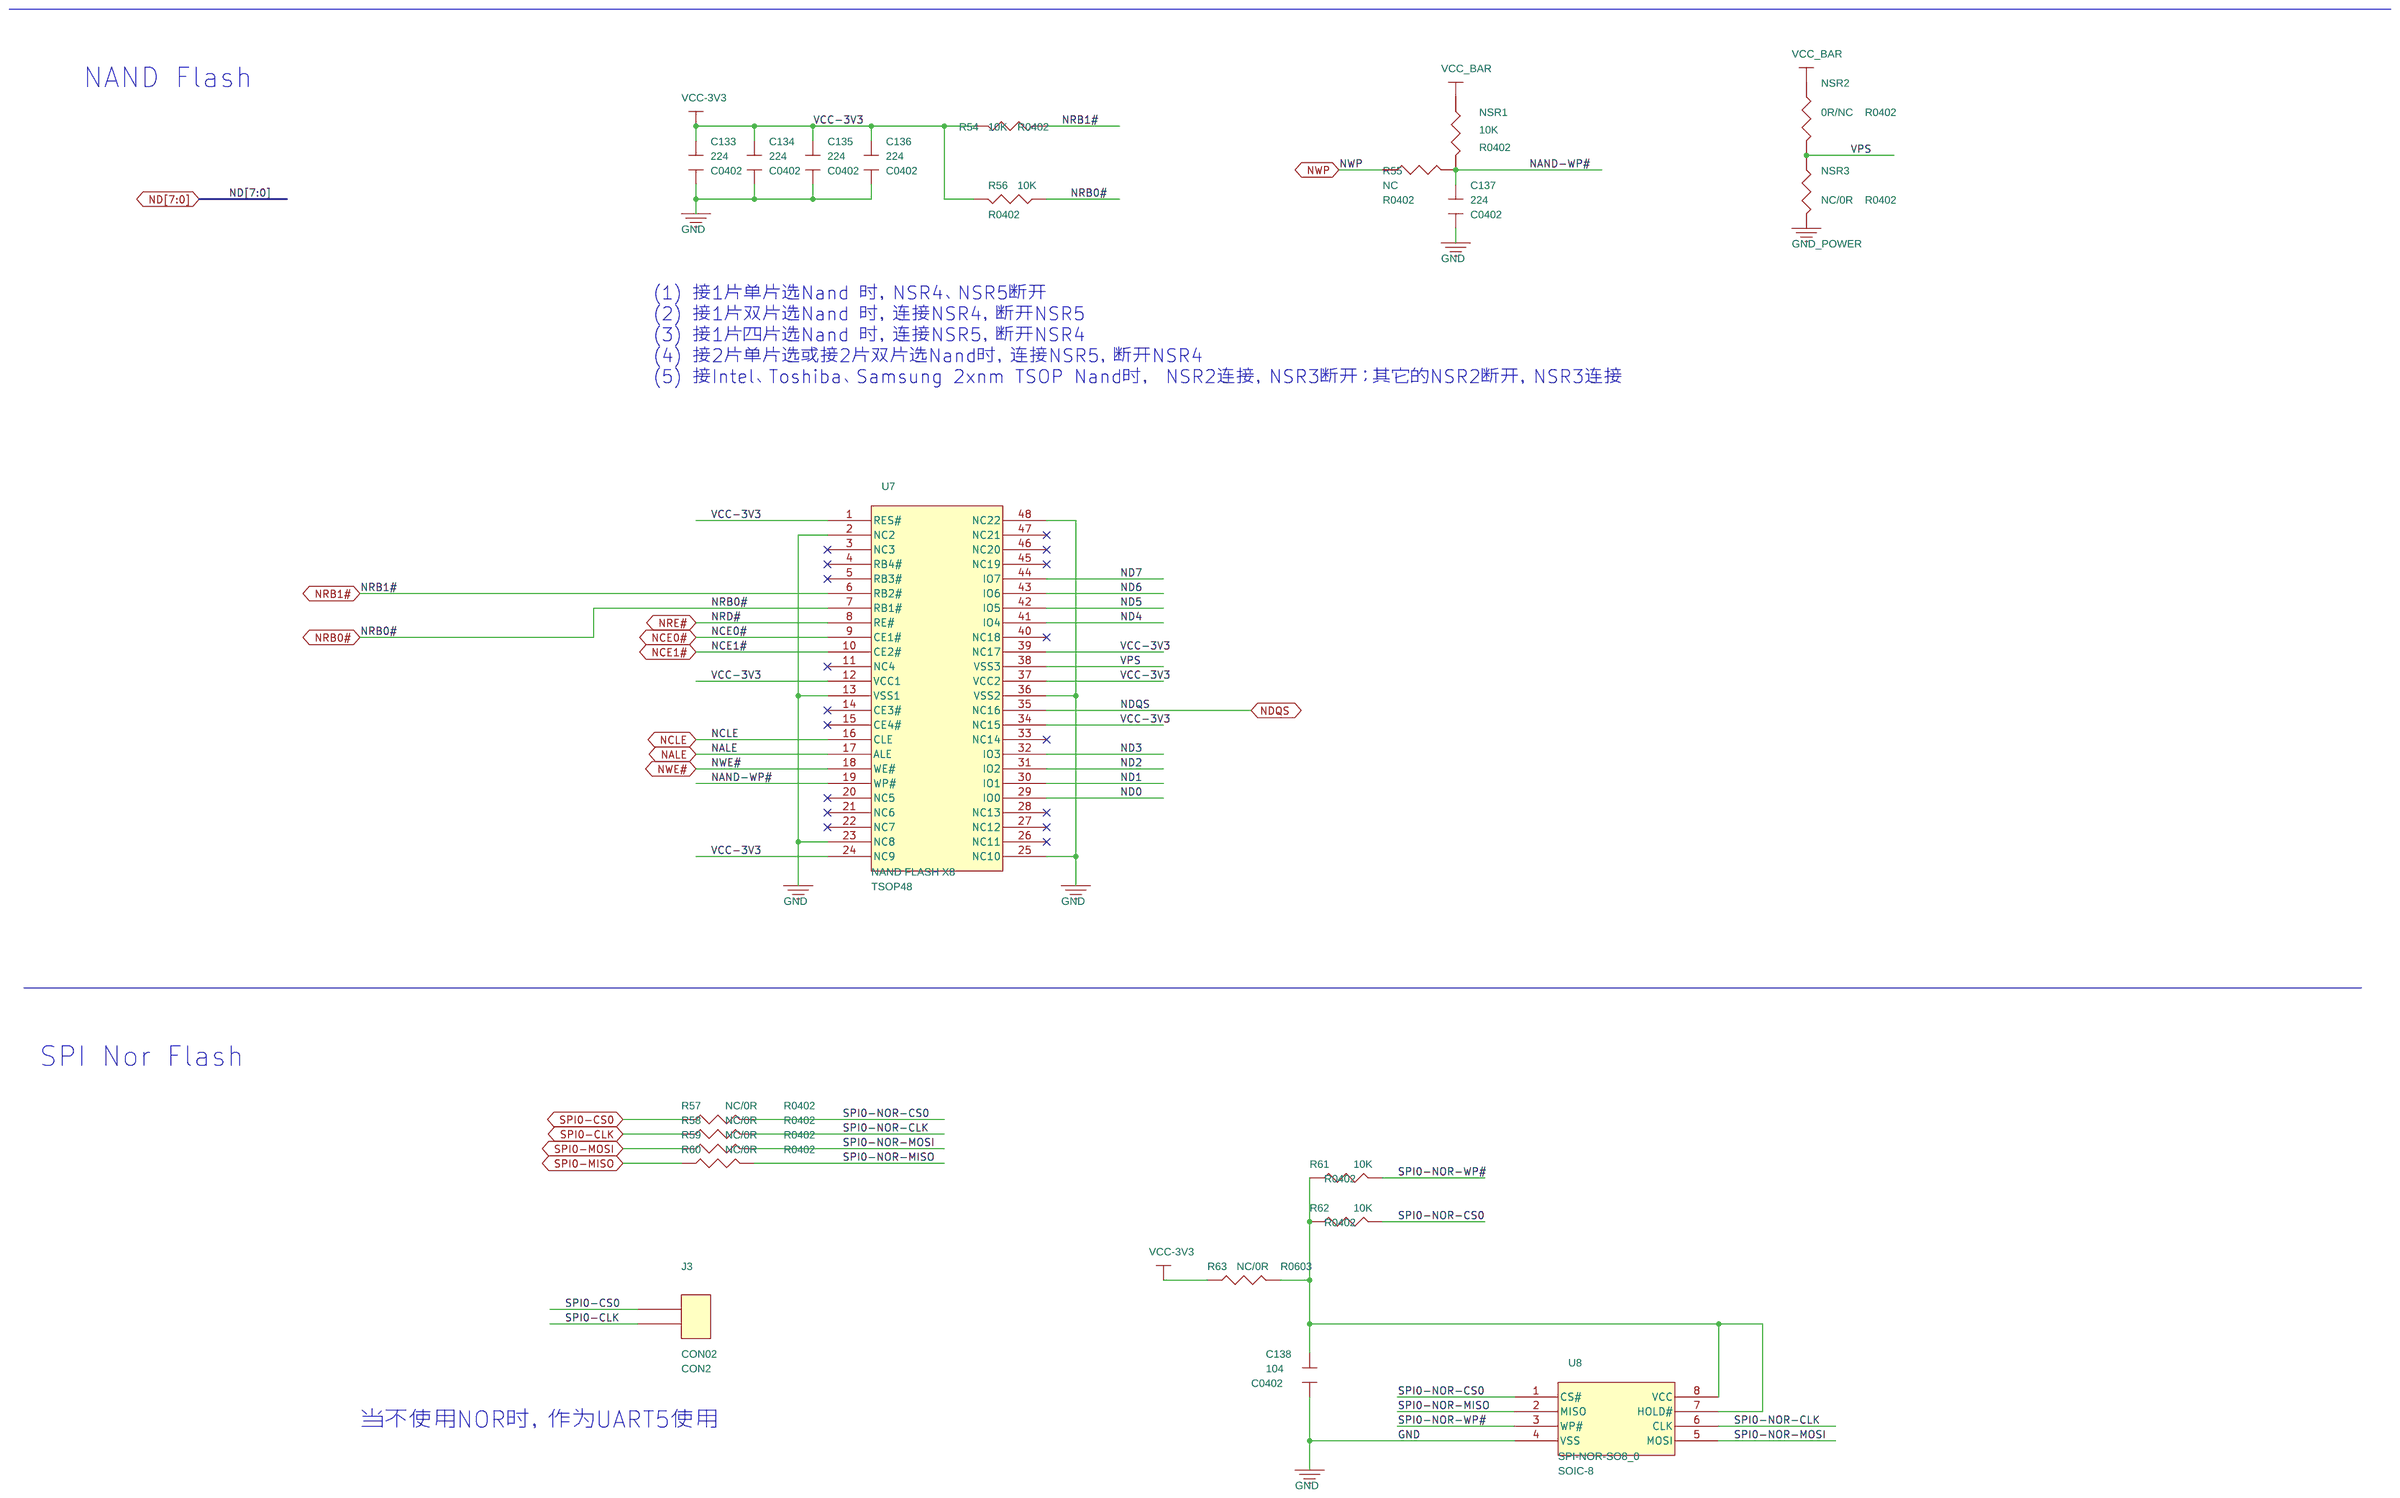
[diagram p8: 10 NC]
10 11 USB-HUB-SD: size A3
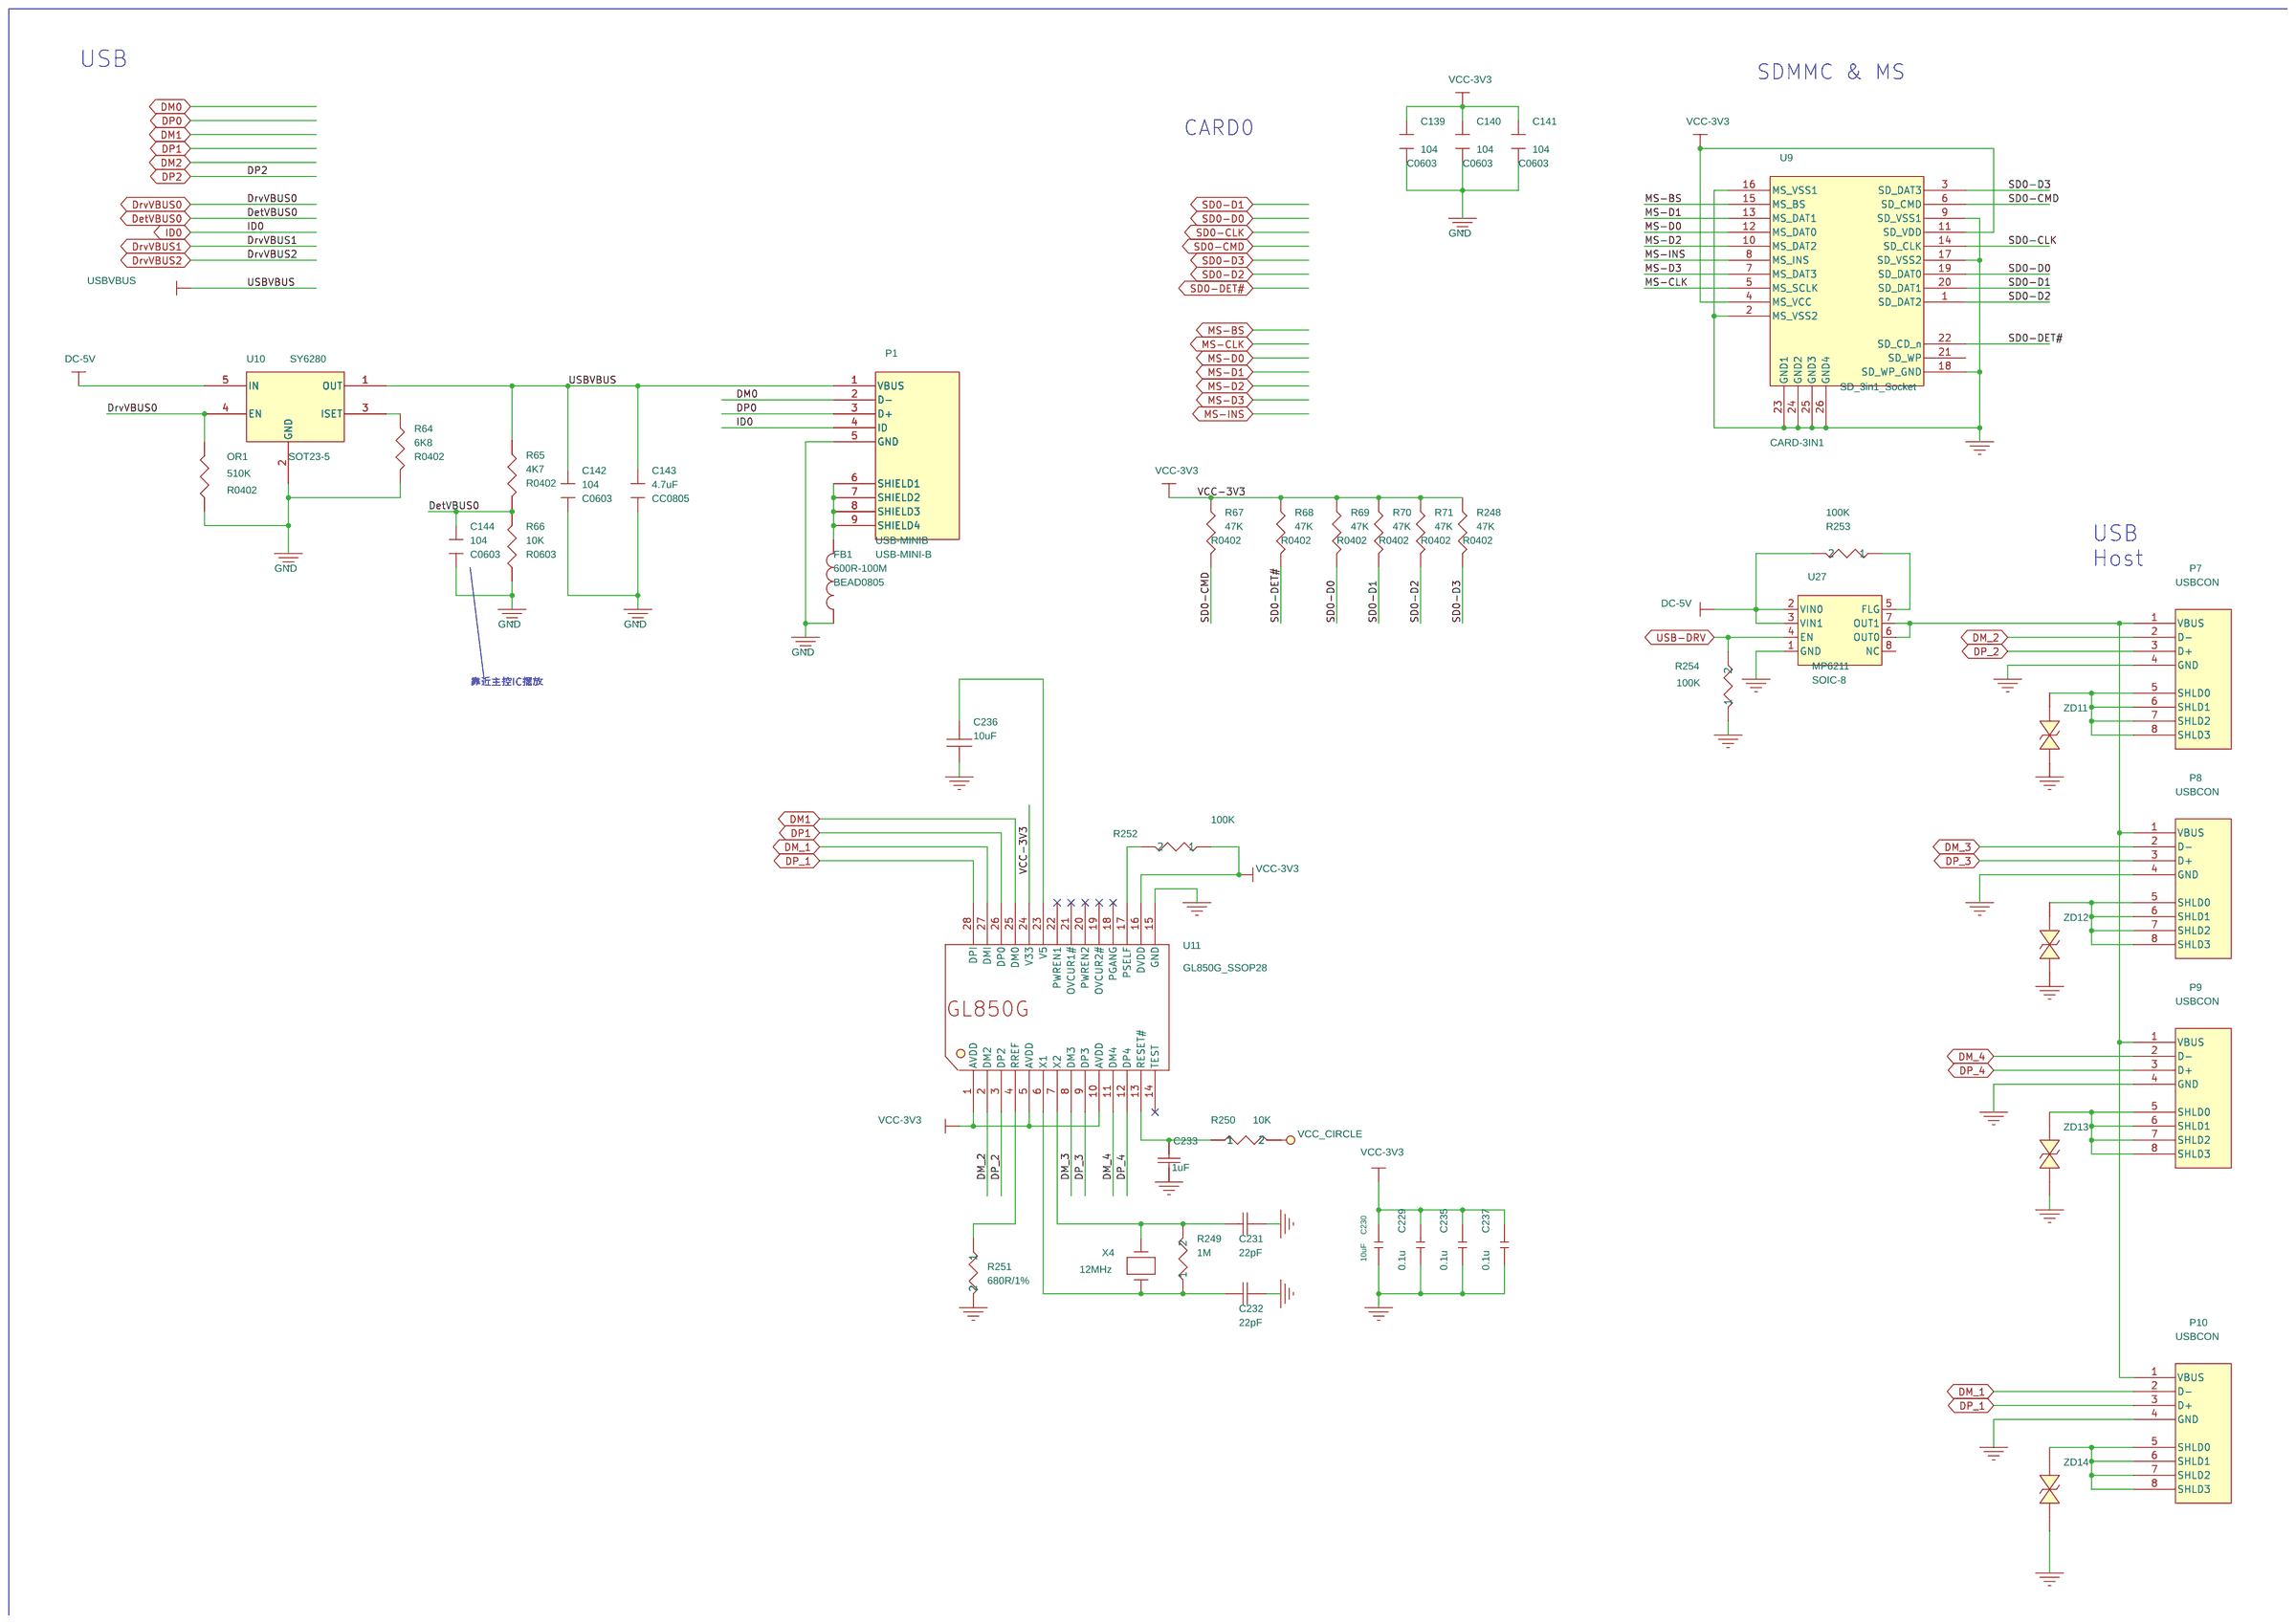
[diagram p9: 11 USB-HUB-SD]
11 12 NC

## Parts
sheet 04 CPU1
R1  240R-1%  [R0402]
sheet 05 CPU2
U1  BGA441-APP  [A10-BGA441]  (sections -1,-2,-3,-4)
sheet 06 BESIDE CPU
C1  224  [C0402]
C2  10uF  [CC0805]
C3  224  [C0402]
C4  224  [C0402]
C5  224  [C0402]
C6  224  [C0402]
C7  224  [C0402]
C8  224  [C0402]
C9  224  [C0402]
C10  224  [C0402]
C11  224  [C0402]
C12  224  [C0402]
C13  224  [C0402]
C14  224  [C0402]
C15  224  [C0402]
C16  10uF  [CC0805]
C17  224  [C0402]
C18  224/NC  [C0402]
C19  224/NC  [C0402]
C20  18pF-1%  [C0402]
C21  18pF-1%  [C0402]
C22  224  [C0402]
C23  224  [C0402]
C24  224  [C0402]
C25  224  [C0402]
C26  224  [C0402]
C27  224  [C0402]
C28  18pF-1%  [C0402]
C29  224  [C0402]
C30  224  [C0402]
C31  224  [C0402]
C32  224  [C0402]
C33  18pF-1%  [C0402]
C34  224  [C0402]
C35  224  [C0402]
C36  224  [C0402]
C37  224  [C0402]
C38  224  [C0402]
C39  224  [C0402]
C40  224  [C0402]
C41  224  [C0402]
C42  224  [C0402]
C43  10uF  [CC0805]
C44  102  [C0402]
C45  224  [C0402]
C46  224  [C0402]
C47  4.7uF  [CC0805]
C48  224  [C0402]
C49  224  [C0402]
C50  102  [C0402]
C51  102  [C0402]
C52  224  [C0402]
C53  10uF  [CC0805]
C54  224  [C0402]
C55  10uF  [CC0805]
C56  102  [C0402]
C57  102  [C0402]
C58  224  [C0402]
C59  224  [C0402]
C60  224  [C0402]
C61  224  [C0402]
C62  224  [C0402]
C63  224  [C0402]
C64  224  [C0402]
C65  10uF  [CC0805]
C66  224  [C0402]
C67  10uF  [CC0805]
C68  224  [C0402]
C69  224  [C0402]
C70  224  [C0402]
C71  10uF  [CC0805]
C72  224  [C0402]
C73  10uF  [CC0805]
C74  224  [C0402]
C75  10uF  [CC0805]
C76  224  [C0402]
C77  474  [C0402]
C78  474  [C0402]
C79  224/NC  [C0402]
C80  224  [C0402]
C81  10uF  [CC0805]
C82  224/NC  [C0402]
R2  1R  [R0603]
R3  1R  [R0603]
R4  10M-1%  [R0402]
R5  200K-1%  [R0402]
R6  0R  [R0402]
R7  1R  [R0603]
R8  1R  [R0603]
R9  1R  [R0402]
R10  1R  [R0603]
R11  1R  [R0603]
R12  2K2  [R0402]
R13  2K2  [R0402]
R14  2K2  [R0402]
R15  2K2  [R0402]
R16  1R  [R0603]
TP1  VCC33-TVIN  [TP_SMD]
TP2  VDD25-TVIN  [TP_SMD]
X1  24MHz  [CRYSTALA]
X2  32768Hz  [CRYSTALA]
sheet 09 DRAM3
C111  224  [C0402]
C112  224  [C0402]
C113  224  [C0402]
C114  224  [C0402]
C115  224  [C0402]
C116  224  [C0402]
C117  224  [C0402]
C118  224  [C0402]
C119  224  [C0402]
C120  224  [C0402]
C121  224  [C0402]
C122  224  [C0402]
C123  224  [C0402]
C124  224  [C0402]
C125  224  [C0402]
C126  224  [C0402]
C127  224  [C0402]
C128  224  [C0402]
C129  224  [C0402]
C130  224  [C0402]
C131  224  [C0402]
C132  224  [C0402]
C146  224  [C0402]
R31  1K-1%  [R0402]
R32  1K-1%  [R0402]
R33  1K-1%  [R0402]
R34  1K-1%  [R0402]
R35  25R  [R0402]
R36  25R  [R0402]
R37  25R  [R0402]
R38  25R  [R0402]
R39  25R  [R0402]
R40  25R  [R0402]
R41  NC  [R0402]
R42  0R  [R0402]
R43  25R  [R0402]
R44  25R  [R0402]
R45  25R  [R0402]
R46  25R  [R0402]
R47  25R  [R0402]
R48  25R  [R0402]
R49  240R-1%  [R0402]
R50  240R-1%  [R0402]
R51  25R  [R0402]
R52  NC/120R  [R0402]
R53  25R  [R0402]
RN1  25R*4  [RN4P-0402]
RN2  25R*4  [RN4P-0402]
RN3  25R*4  [RN4P-0402]
RN4  25R*4  [RN4P-0402]
RN5  25R*4  [RN4P-0402]
RN6  25R*4  [RN4P-0402]
RN7  25R*4  [RN4P-0402]
RN8  25R*4  [RN4P-0402]
TP5  SA0  [TP_SMD050]
TP6  SA1  [TP_SMD050]
TP7  SA2  [TP_SMD050]
TP8  SA3  [TP_SMD050]
TP9  SA4  [TP_SMD050]
TP10  SA5  [TP_SMD050]
TP11  SA6  [TP_SMD050]
TP12  SA7  [TP_SMD050]
TP13  SA8  [TP_SMD050]
TP14  SA9  [TP_SMD050]
TP15  SA10  [TP_SMD050]
TP16  SA11  [TP_SMD050]
TP17  SA12  [TP_SMD050]
TP18  SA13  [TP_SMD050]
TP19  SA14  [TP_SMD050]
TP20  SBA0  [TP_SMD050]
TP21  SBA1  [TP_SMD050]
TP22  SBA2  [TP_SMD050]
TP23  SWE  [TP_SMD050]
TP24  SRAS  [TP_SMD050]
TP25  SCAS  [TP_SMD050]
TP26  SCS0  [TP_SMD050]
TP27  SCKE0  [TP_SMD050]
TP28  SRST  [TP_SMD050]
U5  DDR3-FBGA96  [FBGA96-DDR3]
U6  DDR3-FBGA96  [FBGA96-DDR3]
sheet 10 NC
C133  224  [C0402]
C134  224  [C0402]
C135  224  [C0402]
C136  224  [C0402]
C137  224  [C0402]
C138  104  [C0402]
J3  CON02  [CON2]
NSR1  10K  [R0402]
NSR2  0R/NC  [R0402]
NSR3  NC/0R  [R0402]
R54  10K  [R0402]
R55  NC  [R0402]
R56  10K  [R0402]
R57  NC/0R  [R0402]
R58  NC/0R  [R0402]
R59  NC/0R  [R0402]
R60  NC/0R  [R0402]
R61  10K  [R0402]
R62  10K  [R0402]
R63  NC/0R  [R0603]
U7  NAND FLASH X8  [TSOP48]
U8  SPI-NOR-SO8_0  [SOIC-8]
sheet 11 USB-HUB-SD
C139  104  [C0603]
C140  104  [C0603]
C141  104  [C0603]
C142  104  [C0603]
C143  4.7uF  [CC0805]
C144  104  [C0603]
C229  0.1u  [C0603]
C230  10uF  [C0805]
C231  22pF  [C0603]
C232  22pF  [C0603]
C233  1uF  [C0603]
C235  0.1u  [C0603]
C236  10uF  [C0805]
C237  0.1u  [C0603]
FB1  600R-100M  [BEAD0805]
OR1  510K  [R0402]
P1  USB-MINIB  [USB-MINI-B]
P7  USBCON  [ST-001-03]
P8  USBCON  [ST-001-03]
P9  USBCON  [ST-001-03]
P10  USBCON  [ST-001-03]
R64  6K8  [R0402]
R65  4K7  [R0402]
R66  10K  [R0603]
R67  47K  [R0402]
R68  47K  [R0402]
R69  47K  [R0402]
R70  47K  [R0402]
R71  47K  [R0402]
R248  47K  [R0402]
R249  1M  [R0603]
R250  10K  [R0603]
R251  680R/1%  [R0603]
R252  100K  [R0603]
R253  100K  [R0603]
R254  100K  [R0603]
U9  SD_3in1_Socket  [CARD-3IN1]
U10  SY6280  [SOT23-5]
U11  GL850G_SSOP28  [SSOP28]
U27  MP6211  [SOIC-8]
X4  12MHz  [49U-S]
ZD11  ESD-0603  [0805-ESD]
ZD12  ESD-0603  [0805-ESD]
ZD13  ESD-0603  [0805-ESD]
ZD14  ESD-0603  [0805-ESD]
sheet 22 A10-IO
C175  0.1uF  [C0603]
C177  22uF  [C0603]
C178  22uF  [C0603]
K10  VOL-  [SW2]
K11  VOL+  [SW2]
K12  ENTER/UPGrade  [SW2]
R97  10K  [R0603]
R98  10K  [R0603]
R99  10K  [R0603]
R100  10K  [R0603]
R101  10K  [R0603]
R102  10K  [R0603]
R131  100K  [R0603]
R132  6.8K  [R0603]
R133  8.2K  [R0603]
U13  T15-IO  [T15-IO]
U25  T15-MCU  [24C02]

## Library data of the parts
NSR1-NSR3 OR1 R1-R10 R12-R16 R54-R56 R64-R71 R97-R102 R131-R133 R248 = R
U1 = BGA441-AW1623_13
C1-C43 C50 C51 C55-C67 C69-C71 C79 C80 C82 C133-C137 = CAPACITOR_0: PAGE: 2
C44-C49 = CAPACITOR_0
C52 C54 C68 C72 C81 = CAPACITOR_0: PAGE: 3
C53 C77 C78 C142-C144 = CAPACITOR_v2
C73 C75 C76 = CAPACITOR_v2: PAGE: 2
C74 = CAPACITOR_v2: PAGE: 3
R11 = R_0
TP1 TP2 TP5-TP28 = T_POINT_R
X1 X2 = CRYSTAL_XCOL-3
C111-C132 C146 = CAP_v2
R31-R53 R63 = R1_0805
RN1-RN8 = R-PACK4_1
U5 U6 = DDR3_0
C138-C141 = CAP_Cer_5P-225P
J3 = CON2
R57-R62 = RESISTOR: PAGE: 3
U7 = NAND_FLASH_X8
U8 = SPI-NOR-SO8_0
C229 = CC_2
C230 = CC_3
C231-C233 = CAP_0402
C235 = CC
C236 = CAPACITOR: CAP;Ceramic;X5R;0805;10u;6.3V;+/-20%;2.0x1.25x1.25mm; 1st Vendor: 首科电子; 1st Vendor Price: 0.0283; Availability: Mass Product; Manu Web: http://www.murata.com/; Manufacturer: MURATA; PSpice: C; Package Type: SMT; Part Number: GRM21BR60J106ME19L; Rating: 6.3V; Sample Price: 0.2382; Sample Vendor: 首科电子; Sample Vendor Contract: 徐志斌; Sample Vendor Mail: mikelin@chief-tech.com; Sample Vendor Mobile: 139-1682-5902; Sample Vendor Phone: 021-5239-6355 EXT8014; Sample Vendor Web: http://www.chief-tech.com; Tolerance: +/-20%; UVCHIP Part Number: U3331416101; Vendor: 首科电子; Vendor Contract: 徐志斌; Vendor Mail: mikelin@chief-tech.com; Vendor Mobile: 139-1682-5902; Vendor Phone: 021-5239-6355 EXT8014; Vendor Price: 0.03; Vendor Web: http://www.chief-tech.com; Datasheet: Z:\Datasheet\Discrete\Capacitor\Ceramic\Murata\GRMseries.pdf
C237 = CC_1
FB1 = INDUCTOR
P1 = USB_MINI_SOCKET
P7-P10 = USBCON_ST-001-03: Manufacturer: 惠新锐电子电子有限公司; Package Type: DIP; Part Number: USB00700; Datasheet: Z:\Datasheet\Mechanism\SpecialConnector\USB\惠新锐电子\USB00700 Model.pdf
R249 = RES_0603
R250 = RES_0603_2
R251 = RES_0603_3
R252 = RES_0603_1
R253 = RES_0603_4
R254 = RES_0603_5
U9 = SD_3in1_Socket
U10 = SY6280_2
U11 = FE1_1s_SSOP28_0
U27 = AT24C16B_1
X4 = ZTA
ZD11-ZD14 = ESD
C175 C177 C178 = capacitor: 1st Vendor: 上海爱特信电子科技有限公司; Manu Web: http://www.yageo.com; Manufacturer: YAGEO; Package Type: SMT; Part Number: CC1206KKX55BB226; Vendor Contract: 缪磊; Vendor Mail: miaolei163@163.com; Vendor Mobile: 15951900703; Vendor Phone: 021-33604161; Vendor Web: http://www.attention.com.cn; Datasheet: Z:\Datasheet\Discrete\Capacitor\Ceramic\YAGEO\yageo-UPY-GPHC_X5R_6.3V-to-50V_2++090609.pdf
K10-K12 = SW_PUSH_1
U13 = T15-IO_0
U25 = 24C02_0

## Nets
+3.3V: R97.2 R98.2 R99.2 R100.2 R101.2 R102.2 U25.1(VDD)
+5V: C175.1 C177.1 C178.1 U13.75(VCCIN0) U13.76(VCCIN1) U13.77(VCCIN2)
AGND: C1.1 C2.1 C3.1 C4.1 C5.1 C6.1 C7.1 C8.1 C9.1 C10.1 C11.1 C12.1 C13.1 C14.1 C15.1 C16.1 C17.1 C18.1 C19.1 C20.1 C21.1 C22.1 C23.1 C24.1 C25.1 C26.1 C27.1 C28.1 C29.1 C30.1 C31.1 C32.1 C33.1 C34.1 C35.1 C36.1 C37.1 C38.1 C39.1 C40.1 C41.1 C42.1 C43.1 C44.1 C45.1 C46.1 C47.1 C49.1 C50.1 C51.1 C52.1 C53.1 C54.1 C55.1 C56.1 C57.1 C58.1 C59.1 C60.1 C61.1 C62.1 C63.1 C64.1 C65.1 C66.1 C67.1 C68.1 C69.1 C70.1 C71.1 C72.1 C73.1 C74.1 C75.1 C76.1 C77.1 C78.1 C79.1 C82.1 C111.2 C112.2 C113.2 C114.2 C115.2 C116.2 C117.2 C118.2 C119.2 C120.2 C121.2 C122.2 C123.2 C124.2 C125.2 C126.2 C127.2 C128.2 C131.2 C132.2 C133.1 C134.1 C135.1 C136.1 C137.1 C138.1 C139.1 C140.1 C141.1 C142.1 C143.1 C144.1 C146.2 C175.2 C177.2 C178.2 FB1.1 K10.1 K11.1 K12.1 NSR3.2 OR1.1 P1.5(GND) R1.1 R5.1 R6.2 R33.1 R34.1 R49.1 R50.1 R64.2 R66.1 U1.AA18(GND25_TVIN) U1.G3(GND0_DRAM) U1.G4(GND1_DRAM) U1.H16(TEST) U1.J5(GND2_DRAM) U1.J11(GND0) U1.K5(GND3_DRAM) U1.K11(GND1) U1.K12(GND2) U1.K13(GND3) U1.K14(ULGND) U1.L10(GND4) U1.L11(GND5) U1.L12(GND6) U1.L13(UGND_T) U1.L14(UGND_C) U1.M9(GND0_DLL) U1.M10(GND7) U1.M11(GND8) U1.M12(GND9) U1.M13(GND10) U1.M14(GND0_SATA) U1.N5(GND4_DRAM) U1.N10(GND1_DLL) U1.N11(GND11) U1.N12(GND12) U1.N13(GND1_SATA) U1.N14(GND2_SATA) U1.P5(GND5_DRAM) U1.P10(GND2_DLL) U1.P11(GND13) U1.P12(GND14) U1.P13(GND0_HDMI) U1.P14(GND1_HDMI) U1.P15(PLLGND) U1.R11(GND15) U1.R12(GND16) U1.R13(GND2_HDMI) U1.T9(EFUSE_VDDQ) U1.T11(GND17) U1.T12(GND18) U1.U5(GND6_DRAM) U1.U19(AGND) U1.V5(GND7_DRAM) U1.V19(HPGND) U1.W9(GND0_LVDS) U1.W10(GND1_LVDS) U1.W11(GND2_LVDS) U1.W18(GND33_TVOUT) U1.Y7(GND8_DRAM) U1.Y8(GND9_DRAM) U1.Y18(GND33_TVIN) U5.A9(VSS#9) U5.B1(VSSQ#1) U5.B3(VSS#6) U5.B9(VSSQ#7) U5.D1(VSSQ#2) U5.D8(VSSQ#5) U5.E1(VSS#1) U5.E2(VSSQ#4) U5.E8(VSSQ#6) U5.F9(VSSQ#8) U5.G1(VSSQ#3) U5.G8(VSS#7) U5.G9(VSSQ#9) U5.J2(VSS#5) U5.J8(VSS#8) U5.M1(VSS#2) U5.M9(VSS#10) U5.P1(VSS#3) U5.P9(VSS#11) U5.T1(VSS#4) U5.T9(VSS#12) U6.A9(VSS#9) U6.B1(VSSQ#1) U6.B3(VSS#6) U6.B9(VSSQ#7) U6.D1(VSSQ#2) U6.D8(VSSQ#5) U6.E1(VSS#1) U6.E2(VSSQ#4) U6.E8(VSSQ#6) U6.F9(VSSQ#8) U6.G1(VSSQ#3) U6.G8(VSS#7) U6.G9(VSSQ#9) U6.J2(VSS#5) U6.J8(VSS#8) U6.M1(VSS#2) U6.M9(VSS#10) U6.P1(VSS#3) U6.P9(VSS#11) U6.T1(VSS#4) U6.T9(VSS#12) U7.2(NC2) U7.13(VSS1) U7.23(NC8) U7.25(NC10) U7.36(VSS2) U7.48(NC22) U8.4(VSS) U9.2(MS_VSS2) U9.9(SD_VSS1) U9.16(MS_VSS1) U9.17(SD_VSS2) U9.18(SD_WP_GND) U9.23(GND1) U9.24(GND2) U9.25(GND3) U9.26(GND4) U10.2(GND) U13.78(AGND0) U13.79(AGND1) U13.80(AGND2) U13.81(AGND3) U13.82(AGND4) U13.83(AGND5) U13.84(AGND6) U13.85(AGND7) U13.86(AGND8) U13.87(AGND9) U13.88(AGND10) U13.89(AGND11) U13.90(AGND12) U13.91(AGND13) U13.92(AGND14) U13.93(AGND15) U25.8(GND) X1.3(Shield) X2.3(Shield) ; also on sheet 12 13 14 16 17 18 21 22
AVCC: U1.T19(AVCC) ; also on sheet 14 21
AVCC (page 22 A10-IO): R131.1 U13.36(AVCC-3V)
GND_POWER: C229.1 C230.1 C231.2 C232.2 C233.2 C235.1 C236.1 C237.1 P7.4(GND) P8.4(GND) P9.4(GND) P10.4(GND) R251.2 R254.1 U11.15(GND) U27.1(GND) ZD11.1 ZD12.1 ZD13.1 ZD14.1
VCC33-TVIN: C73.2 C74.2 R11.2 TP1.1(TP) U1.W16(VCC33_TVIN)
VCC-2V5: R10.1 ; also on sheet 22
VDD12-SATA: U1.M15(VDD12_0_SATA) U1.M16(VDD12_1_SATA)
VDD25-SATA: U1.N15(VDD25_0_SATA) U1.N16(VDD25_1_SATA)
VDD25-TVIN: C75.2 C76.2 R10.2 TP2.1(TP) U1.W17(VDD25_TVIN)
BL-EN: U13.98(LCD0-BL-EN)
CK: R51.1 R52.2 U5.J7(CK) U6.J7(CK)
CK#: R52.1 R53.1 U5.K7(CK#) U6.K7(CK#)
CLK32K-IN: C21.2 R4.1 U1.F1(CLK32K_IN) X2.1
CLK32K-OUT: C33.2 R4.2 U1.F2(CLK32K_OUT) X2.2
CPUVDD: C59.2 C60.2 C61.2 C62.2 C63.2 C64.2 U1.H11(VDD0_CPU) U1.H12(VDD1_CPU) U1.H13(VDD2_CPU) U1.H14(VDD3_CPU) U1.J12(VDD4_CPU) U1.J13(VDD5_CPU) ; also on sheet 21
CPUVDD (page 22 A10-IO): U13.34(CPUVDD0) U13.35(CPUVDD1)
CSI0-D0: U1.C23(TS0_D0/CSI0_D0/PE4)
CSI0-D1: U1.C22(TS0_D1/CSI0_D1/PE5)
CSI0-D2: U1.B23(TS0_D2/CSI0_D2/PE6)
CSI0-D3: U1.B22(TS0_D3/CSI0_D3/PE7)
CSI0-D4: U1.A23(TS0_D4/CSI0_D4/PE8)
CSI0-D5: U1.A22(TS0_D5/CSI0_D5/PE9)
CSI0-D6: U1.B21(TS0_D6/CSI0_D6/PE10)
CSI0-D7: U1.A21(TS0_D7/CSI0_D7/PE11)
CSI0-HSYNC: U1.D23(TS0_SYNC/CSI0_HSYNC/PE2)
CSI0-IO-2V8: C69.2 U1.F19(VCC_CSI0) ; also on sheet 21
CSI0-MCLK: U1.E22(TS0_ERR/CSI0_MCLK/PE1)
CSI0-PCLK: U1.E23(TS0_CLK/CSI0_PCLK/PE0)
CSI0-PIO0: U1.A1(LCD1_D15/ATAD11/KP_IN5/SMC_VPPPP/EINT15/CSI1_D15/PH15)
CSI0-PIO1: U1.D2(LCD1_D20/ATAOE/CAN_TX/EINT20/CSI1_D20/PH20)
CSI0-VSYNC: U1.D22(TS0_DVLD/CSI0_VSYNC/PE3)
CSI1-D0: U1.D20(TS1_D0/CSI1_D0/SDC1_D2/CSI0_D8/PG4)
CSI1-D1: U1.C21(TS1_D1/CSI1_D1/SDC1_D3/CSI0_D9/PG5)
CSI1-D2: U1.E19(TS1_D2/CSI1_D2/UART3_TX/CSI0_D10/PG6)
CSI1-D3: U1.C20(TS1_D3/CSI1_D3/UART3_RX/CSI0_D11/PG7)
CSI1-D4: U1.D19(TS1_D4/CSI1_D4/UART3_RTS/CSI0_D12/PG8)
CSI1-D5: U1.C19(TS1_D5/CSI1_D5/UART3_CTS/CSI0_D13/PG9)
CSI1-D6: U1.D18(TS1_D6/CSI1_D6/UART4_TX/CSI0_D14/PG10)
CSI1-D7: U1.C18(TS1_D7/CSI1_D7/UART4_RX/CSI0_D15/PG11)
CSI1-HSYNC: U1.E20(TS1_SYNC/CSI1_HSYNC/SDC1_D0/PG2)
CSI1-IO-2V8: C70.2 U1.E18(VCC_CSI1) ; also on sheet 21
CSI1-L1-D0: U1.A6(LCD1_D0/ATAA0/UART3_TX/EINT0/CSI1_D0/PH0)
CSI1-L1-D1: U1.B6(LCD1_D1/ATAA1/UART3_RX/EINT1/CSI1_D1/PH1)
CSI1-L1-D2: U1.C6(LCD1_D2/ATAA2/UART3_RTS/EINT2/CSI1_D2/PH2)
CSI1-L1-D3: U1.A5(LCD1_D3/ATAIRQ/UART3_CTS/EINT3/CSI1_D3/PH3)
CSI1-L1-D4: U1.B5(LCD1_D4/ATAD0/UART4_TX/EINT4/CSI1_D4/PH4)
CSI1-L1-D5: U1.C5(LCD1_D5/ATAD1/UART4_RX/EINT5/CSI1_D5/PH5)
CSI1-L1-HSYNC: U1.F3(LCD1_HSYNC/ATAIOR/KP_OUT6/SDC1_D2/CSI1_HSYNC/PH26)
CSI1-L1-MCLK: U1.E4(LCD1_DE/ATAIORDY/KP_OUT5/SDC1_D1/CSI1_FIELD/PH25)
CSI1-L1-PCLK: U1.E3(LCD1_CLK/ATACS1/KP_OUT4/SDC1_D0/CSI1_PCLK/PH24)
CSI1-L1-VSYNC: U1.F4(LCD1_VSYNC/ATAIOW/KP_OUT7/SDC1_D3/CSI1_VSYNC/PH27)
CSI1-MCLK: U1.E21(TS1_ERR/CSI1_MLCK/SDC1_CLK/PG1)
CSI1-PCLK: U1.F20(TS1_CLK/CSI1_PCLK/SDC1_CMD/PG0)
CSI1-PIO0: U1.D3(LCD1_D21/ATADREQ/CAN_RX/EINT21/CSI1_D21/PH21)
CSI1-PIO1: U1.E1(LCD1_D22/ATADACK/KP_OUT2/SDC1_CMD/CSI1_D22/PH22)
CSI1-VSYNC: U1.D21(TS1_DVLD/CSI1_VSYNC/SDC1_D1/PG3)
DC-5V: R253.2 U10.5(IN) U27.2(VIN0) U27.3(VIN1) ; also on sheet 12 16 17 18 21 22
DetVBUS0: C144.2 R65.2 R66.2 U1.E15(EINT30/SPI1_MOSI/UART2_TX/PI18)
DLLVDD: C2.2 C3.2 C4.2 C5.2 R2.2 U1.M8(VDD0_DLL) U1.N9(VDD1_DLL) U1.P9(VDD2_DLL)
DM0: P1.2(D-) U1.N20(DM0) U13.25(DM0)
DM1: U1.P20(DM1) U11.25(DM0) U13.23(DM1)
DM2: U1.R20(DM2) U13.21(DM2)
DM_1: P10.2(D-) U11.27(DMI)
DM_2: P7.2(D-) U11.2(DM2)
DM_3: P8.2(D-) U11.8(DM3)
DM_4: P9.2(D-) U11.11(DM4)
DP0: P1.3(D+) U1.N21(DP0) U13.26(DP0)
DP1: U1.P21(DP1) U11.26(DP0) U13.24(DP1)
DP2: U1.R21(DP2) U13.22(DP2)
DP_1: P10.3(D+) U11.28(DPI)
DP_2: P7.3(D+) U11.3(DP2)
DP_3: P8.3(D+) U11.9(DP3)
DP_4: P9.3(D+) U11.12(DP4)
DQ0: RN8.2(R2) U5.E3(DQL0)
DQ1: RN6.2(R2) U5.F7(DQL1)
DQ2: RN8.3(R3) U5.F2(DQL2)
DQ3: RN6.3(R3) U5.F8(DQL3)
DQ4: RN6.4(R4) U5.H3(DQL4)
DQ5: RN8.4(R4) U5.H8(DQL5)
DQ6: RN6.1(R1) U5.G2(DQL6)
DQ7: RN8.1(R1) U5.H7(DQL7)
DQ8: RN7.2(R2) U5.D7(DQU0)
DQ9: RN5.2(R2) U5.C3(DQU1)
DQ10: RN7.3(R3) U5.C8(DQU2)
DQ11: RN5.3(R3) U5.C2(DQU3)
DQ12: RN5.4(R4) U5.A7(DQU4)
DQ13: RN7.4(R4) U5.A2(DQU5)
DQ14: RN5.1(R1) U5.B8(DQU6)
DQ15: RN7.1(R1) U5.A3(DQU7)
DQ16: RN3.2(R2) U6.E3(DQL0)
DQ17: RN4.2(R2) U6.F7(DQL1)
DQ18: RN3.3(R3) U6.F2(DQL2)
DQ19: RN4.3(R3) U6.F8(DQL3)
DQ20: RN4.4(R4) U6.H3(DQL4)
DQ21: RN3.4(R4) U6.H8(DQL5)
DQ22: RN4.1(R1) U6.G2(DQL6)
DQ23: RN3.1(R1) U6.H7(DQL7)
DQ24: RN2.2(R2) U6.D7(DQU0)
DQ25: RN1.2(R2) U6.C3(DQU1)
DQ26: RN2.3(R3) U6.C8(DQU2)
DQ27: RN1.3(R3) U6.C2(DQU3)
DQ28: RN1.4(R4) U6.A7(DQU4)
DQ29: RN2.4(R4) U6.A2(DQU5)
DQ30: RN1.1(R1) U6.B8(DQU6)
DQ31: RN2.1(R1) U6.A3(DQU7)
DQM0: R47.1 U5.E7(DML)
DQM1: R48.1 U5.D3(DMU)
DQM2: R39.1 U6.E7(DML)
DQM3: R40.1 U6.D3(DMU)
DQS0: R43.1 U5.F3(DQSL)
DQS0#: R44.1 U5.G3(DQSL#)
DQS1: R45.1 U5.C7(DQSU)
DQS1#: R46.1 U5.B7(DQSU#)
DQS2: R35.1 U6.F3(DQSL)
DQS2#: R36.1 U6.G3(DQSL#)
DQS3: R37.1 U6.C7(DQSU)
DQS3#: R38.1 U6.B7(DQSU#)
DRAM-REF: C129.2 C131.1 C146.1 R31.1 R33.2 U5.H1(VREFDQ) U5.M8(VREFCA) U6.H1(VREFDQ) U6.M8(VREFCA)
DRAM-VCC: C6.2 C7.2 C8.2 C9.2 C10.2 C11.2 C12.2 C13.2 C14.2 C15.2 C111.1 C112.1 C113.1 C114.1 C115.1 C116.1 C117.1 C118.1 C119.1 C120.1 C121.1 C122.1 C123.1 C124.1 C125.1 C126.1 C127.1 C128.1 C129.1 C130.1 R31.2 R32.2 U1.G5(VCC0_DRAM) U1.H5(VCC1_DRAM) U1.L5(VCC2_DRAM) U1.M5(VCC3_DRAM) U1.R5(VCC4_DRAM) U1.T5(VCC5_DRAM) U1.W5(VCC6_DRAM) U1.W6(VCC7_DRAM) U1.W7(VCC8_DRAM) U1.Y6(VCC9_DRAM) U5.A1(VDDQ#1) U5.A8(VDDQ#6) U5.B2(VDD#3) U5.C1(VDDQ#2) U5.C9(VDDQ#9) U5.D2(VDDQ#4) U5.D9(VDD#7) U5.E9(VDDQ#8) U5.F1(VDDQ#3) U5.G7(VDD#5) U5.H2(VDDQ#5) U5.H9(VDDQ#7) U5.K2(VDD#4) U5.K8(VDD#6) U5.N1(VDD#1) U5.N9(VDD#8) U5.R1(VDD#2) U5.R9(VDD#9) U6.A1(VDDQ#1) U6.A8(VDDQ#6) U6.B2(VDD#3) U6.C1(VDDQ#2) U6.C9(VDDQ#9) U6.D2(VDDQ#4) U6.D9(VDD#7) U6.E9(VDDQ#8) U6.F1(VDDQ#3) U6.G7(VDD#5) U6.H2(VDDQ#5) U6.H9(VDDQ#7) U6.K2(VDD#4) U6.K8(VDD#6) U6.N1(VDD#1) U6.N9(VDD#8) U6.R1(VDD#2) U6.R9(VDD#9) ; also on sheet 22
DrvVBUS0: OR1.2 U1.C3(LCD1_D12/ATAD8/PS2_SCK1/EINT12/CSI1_D12/PH12) U10.4(EN)
DrvVBUS1: U1.E2(LCD1_D23/ATACS0/KP_OUT3/SDC1_CLK/CSI1_D23/PH23)
DrvVBUS2: U1.B2(LCD1_D14/ATAD10/KP_IN4/SMC_VPPEN/EINT14/CSI1_D14/PH14)
DSODT0: R41.1 U5.K1(ODT) U6.K1(ODT)
DSRST: R42.1 TP28.1(TP) U5.T2(RESET) U6.T2(RESET)
ECOL: U1.D13(ECOL/CAN_TX/UART1_DCD/PA16) U13.56(ECOL) ; also on sheet 13
ECRS: U1.E12(ECRS/UART7_RX/UART1_DSR/PA15) U13.61(ECRS) ; also on sheet 13
EMDC: U1.E10(EMDC/UART1_RX/PA11) U13.59(EMDC) ; also on sheet 13
EMDIO: U1.D11(EMDIO/UART6_TX/UART1_RTS/PA12) U13.58(EMDIO) ; also on sheet 13
ERESET#: U1.F23(NCE2/PC17)
ERXCK: U1.D9(ERXCK/SPI3_MISO/PA8) U13.67(ERXCK) ; also on sheet 13
ERXD0: U1.E6(ERXD0/SPI1_MISO/PA3) U13.63(ERXD0) ; also on sheet 13
ERXD1: U1.D6(ERXD1/SPI1_MOSI/PA2) U13.64(ERXD1) ; also on sheet 13
ERXD2: U1.E5(ERXD2/SPI1_CLK/PA1) U13.65(ERXD2) ; also on sheet 13
ERXD3: U1.D5(ERXD3/SPI1_CS0/PA0) U13.66(ERXD3) ; also on sheet 13
ERXDV: U1.D10(ERXDV/UART1_TX/PA10) U13.62(ERXDV) ; also on sheet 13
ERXERR: U1.E9(ERXERR/SPI3_CS1/PA9) U13.60(ERXERR) ; also on sheet 13
ETXCK: U1.D12(ETXCK/UART7_TX/UART1_DTR/PA14) U13.57(ETXCK) ; also on sheet 13
ETXD0: U1.E8(ETXD0/SPI3_MOSI/PA7) U13.54(ETXD0) ; also on sheet 13
ETXD1: U1.D8(ETXD1/SPI3_CLK/PA6) U13.53(ETXD1) ; also on sheet 13
ETXD2: U1.E7(ETXD2/SPI3_CS0/PA5) U13.52(ETXD2) ; also on sheet 13
ETXD3: U1.D7(ETXD3/SPI1_CS1/PA4) U13.51(ETXD3) ; also on sheet 13
ETXEN: U1.E11(ETXEN/UART6_RX/UART1_CTS/PA13) U13.50(ETXEN) ; also on sheet 13
ETXERR: U1.C13(ETXERR/CAN_RX/UART1_RING/PA17) ; also on sheet 13
FMINL: U1.Y20(FMINL)
FMINR: U1.Y21(FMINR)
GPIO12_SI: U13.40(SPI0-MOSI)
GPIO13_SO: U13.42(SPI0-MISO)
GPIO14_CLK: U13.43(SPI0-CLK)
GPIO15_CS: U13.41(SPI0-CS0)
HCEC: U1.P23(CEC_HDMI) ; also on sheet 12
HGND: C80.1 C81.1
HHPD: U1.P22(HPD_HDMI) ; also on sheet 12
HPCOM: U1.AA19(HPCOM)
HPCOMFB: U1.AA20(HPCOMFB)
HPL: U1.Y19(HPOUTL) U13.3(HPL) ; also on sheet 17
HPR: U1.W19(HPOUTR) U13.4(HPR) ; also on sheet 17
HPVCC: C55.2 C58.2 U1.AC19(HPVCC)
HPVCCIN: C1.2 C34.2 C35.2 C36.2 C37.2 C38.2 C39.2 C40.2 C41.2 C42.2 C52.2 C133.2 C134.2 C135.2 C136.2 C139.2 C140.2 C141.2 C229.2 C230.2 C235.2 C237.2 NSR1.1 NSR2.1 R3.1 R8.1 R9.1 R11.1 R12.1 R13.1 R14.1 R15.1 R16.1 R54.2 R56.2 R63.1 R67.1 R68.1 R69.1 R70.1 R71.1 R248.1 R250.2 R252.1 U1.AB19(HPVCCIN) U1.H8(VCC0) U1.H9(VCC1) U1.H10(VCC2) U1.H15(VCC3) U1.H19(NAND_VCC0) U1.J8(VCC4) U1.J9(VCC5) U1.J10(VCC6) U1.J14(VCC7) U1.J19(NAND_VCC1) U1.N19(VCC_CARD) U1.W12(VCC0_LVDS) U1.W13(VCC1_LVDS) U1.W14(VCC2_LVDS) U7.1(RES#) U7.12(VCC1) U7.24(NC9) U7.34(NC15) U7.37(VCC2) U7.39(NC17) U9.4(MS_VCC) U9.11(SD_VDD) U11.1(AVDD) U11.5(AVDD) U11.10(AVDD) U11.16(DVDD) U11.24(V33) ; also on sheet 13 14 17 21 22
HSCL: U1.R23(SCL_HDMI) ; also on sheet 12
HSDA: U1.R22(SDA_HDMI) ; also on sheet 12
HTX0N: U1.V22(TX0N_HDMI) ; also on sheet 12
HTX0P: U1.V23(TX0P_HDMI) ; also on sheet 12
HTX1N: U1.U22(TX1N_HDMI) ; also on sheet 12
HTX1P: U1.U23(TX1P_HDMI) ; also on sheet 12
HTX2N: U1.T22(TX2N_HDMI) ; also on sheet 12
HTX2P: U1.T23(TX2P_HDMI) ; also on sheet 12
HTXCN: U1.W22(TXCN_HDMI) ; also on sheet 12
HTXCP: U1.W23(TXCP_HDMI) ; also on sheet 12
HVP: C80.2 C81.2 R16.2 U1.T13(VP_HDMI)
HVREGIO1: C79.2 U1.T14(VREGIO1_HDMI)
HVREGIO2: C82.2 U1.R14(VREGIO2_HDMI)
I2S-BCLK: U1.A12(I2S_BCLK/AC97_BCLK/PB6)
I2S-DI: U1.C9(I2S_DI/AC97_DI/SPDIF_DI/PB12)
I2S-DO0: U1.A11(I2S_DO0/AC97_DO/PB8)
I2S-DO1: U1.C12(I2S_DO1/PB9)
I2S-DO2: U1.C11(I2S_DO2/PB10)
I2S-DO3: U1.C10(I2S_DO3/PB11)
I2S-LRCK: U1.B12(I2S_LRCK/AC97_SYNC/PB7)
I2S-MCLK: U1.B13(I2S_MCLK/AC97_MCLK/PB5)
ID0: P1.4(ID) U1.D14(EINT31/SPI1_MISO/UART2_RX/PI19)
INTVDD: C22.2 C23.2 C24.2 C25.2 C26.2 C27.2 C29.2 C30.2 C31.2 C32.2 R2.1 R7.1 U1.J15(VDD0_INT) U1.J16(VDD1_INT) U1.K9(VDD2_INT) U1.K10(VDD3_INT) U1.K15(VDD4_INT) U1.L8(VDD5_INT) U1.L9(VDD6_INT) U1.R9(VDD7_INT) U1.R10(VDD8_INT) U1.T8(VDD9_INT) ; also on sheet 21
INTVDD (page 22 A10-IO): U13.37(INTVDD0) U13.38(INTVDD1)
IR-RX: U1.A13(IR0_RX/PB4) ; also on sheet 14
JTAG-CK: U1.B10(JTAG_CK0/SPI2_CLK/PB15)
JTAG-DI: U1.B9(JTAG_DI0/SPI2_MISO/PB17)
JTAG-DO: U1.A9(JTAG_DO0/SPI2_MOSI/PB16)
JTAG-MS: U1.A10(JTAG_MS0/SPI2_CS0/PB14)
JTAG-SEL: U1.T10(JTAG_SEL) ; also on sheet 13
LCD0-CLK: U1.Y9(LCD0_CLK/SMC_VCCEN/PD24) U13.106(LCD0-CLK)
LCD0-D0: U1.AB15(LCD0_D0/LVDS0_VP0/PD0) U13.130(LCD0-D0)
LCD0-D1: U1.AC15(LCD0_D1/LVDS0_VN0/PD1) U13.132(LCD0-D1)
LCD0-D2: U1.AB14(LCD0_D2/LVDS0_VP1/PD2) U13.126(LCD0-D2)
LCD0-D3: U1.AC14(LCD0_D3/LVDS0_VN1/PD3) U13.127(LCD0-D3)
LCD0-D4: U1.AB13(LCD0_D4/LVDS0_VP2/PD4) U13.122(LCD0-D4)
LCD0-D5: U1.AC13(LCD0_D5/LVDS0_VN2/PD5) U13.123(LCD0-D5)
LCD0-D6: U1.AB12(LCD0_D6/LVDS0_VPC/PD6) U13.120(LCD0-D6)
LCD0-D7: U1.AC12(LCD0_D7/LVDS0_VNC/PD7) U13.121(LCD0-D7)
LCD0-D8: U1.AB11(LCD0_D8/LVDS0_VP3/PD8) U13.116(LCD0-D8)
LCD0-D9: U1.AC11(LCD0_D9/LVDS0_VN3/PD9) U13.117(LCD0-D9)
LCD0-D10: U1.Y15(LCD0_D10/LVDS1_VP0/PD10) U13.131(LCD0-D10)
LCD0-D11: U1.AA15(LCD0_D11/LVDS1_VN0/PD11) U13.133(LCD0-D11)
LCD0-D12: U1.Y14(LCD0_D12/LVDS1_VP1/PD12) U13.128(LCD0-D12)
LCD0-D13: U1.AA14(LCD0_D13/LVDS1_VN1/PD13) U13.129(LCD0-D13)
LCD0-D14: U1.Y13(LCD0_D14/LVDS1_VP2/PD14) U13.124(LCD0-D14)
LCD0-D15: U1.AA13(LCD0_D15/LVDS1_VN2/PD15) U13.125(LCD0-D15)
LCD0-D16: U1.Y12(LCD0_D16/LVDS1_VPC/PD16) U13.118(LCD0-D16)
LCD0-D17: U1.AA12(LCD0_D17/LVDS1_VNC/PD17) U13.119(LCD0-D17)
LCD0-D18: U1.Y11(LCD0_D18/LVDS1_VP3/PD18) U13.114(LCD0-D18)
LCD0-D19: U1.AA11(LCD0_D19/LVDS1_VN3/PD19) U13.115(LCD0-D19)
LCD0-D20: U1.Y10(LCD0_D20/CSI1_MCLK/PD20) U13.110(LCD0-D20)
LCD0-D21: U1.AA10(LCD0_D21/SMC_VPPEN/PD21) U13.111(LCD0-D21)
LCD0-D22: U1.AB10(LCD0_D22/SMC_VPPPP/PD22) U13.112(LCD0-D22)
LCD0-D23: U1.AC10(LCD0_D23/SMC_DET/PD23) U13.113(LCD0-D23)
LCD0-DE: U1.AA9(LCD0_DE/SMC_RST/PD25) U13.107(LCD0-DE)
LCD0-HS: U13.108(LCD0-HSYNC)
LCD0-HSYNC: U1.AB9(LCD0_HSYNC/SMC_SLK/PD26)
LCD0-PWR: U13.105(LCD0-PWR)
LCD0-VS: U13.109(LCD0-VSYNC)
LCD0-VSYNC: U1.AC9(LCD0_VSYNC/SMC_SDA/PD27)
LCD-PIO0: U1.A20(GPS_CLK/PI0)
LCD-PIO1: U1.B20(GPS_SIGN/PI1)
LCD-PIO2: U1.A19(GPS_MAG/PI2)
LCD-PWR: U1.G19(SPI0_CS0/PC23)
LINEINL: U1.AB20(LINEINL)
LINEINR: U1.AB21(LINEINR)
LRADC0: C44.2 U1.AB23(LRADC0) ; also on sheet 14
MICIN1: U1.AC20(MICIN1)
MICIN2: U1.AC21(MICIN2)
MICM: C48.1 R6.1
MS-BS: U1.A4(LCD1_D6/ATAD2/UART5_TX/MS_BS/EINT6/CSI1_D6/PH6) U9.15(MS_BS)
MS-CLK: U1.B4(LCD1_D7/ATAD3/UART5_RX/MS_CLK/EINT7/CSI1_D7_/PH7) U9.5(MS_SCLK)
MS-D0: U1.C4(LCD1_D8/ATAD4/KP_IN0/MS_D0/EINT8/CSI1_D8/PH8) U9.12(MS_DAT0)
MS-D1: U1.D4(LCD1_D9/ATAD5/KP_IN1/MS_D1/EINT9/CSI1_D9/PH9) U9.13(MS_DAT1)
MS-D2: U1.A3(LCD1_D10/ATAD6/KP_IN2/MS_D2/EINT10/CSI1_D10/PH10) U9.10(MS_DAT2)
MS-D3: U1.B3(LCD1_D11/ATAD7/KP_IN3/MS_D3/EINT11/CSI1_D11/PH11) U9.7(MS_DAT3)
MS-INS: U1.F22(NCE3/PC18) U9.8(MS_INS)
MUTE: U1.B14(IR0_TX/SPDIF_MCLK/STANBYWFI/PB3) ; also on sheet 17
NALE: U1.M22(NALE/SPI0_MISO/PC1) U7.17(ALE)
NAND-WP#: C137.2 NSR1.2 R55.2 U7.19(WP#)
NC: U27.8(NC)
NCE0#: U1.K23(NCE0/PC4) U7.9(CE1#)
NCE1#: U1.L22(NCE1/PC3) U7.10(CE2#)
NCLE: U1.L23(NCLE/SPI0_CLK/PC2) U7.16(CLE)
ND0: U1.H23(NDQ0/SDC2_D0/PC8) U7.29(IO0)
ND1: U1.H22(NDQ1/SDC2_D1/PC9) U7.30(IO1)
ND2: U1.G23(NDQ2/SDC2_D2/PC10) U7.31(IO2)
ND3: U1.G22(NDQ3/SDC2_D3/PC11) U7.32(IO3)
ND4: U1.H21(NDQ4/PC12) U7.41(IO4)
ND5: U1.H20(NDQ5/PC13) U7.42(IO5)
ND6: U1.G21(NDQ6/PC14) U7.43(IO6)
ND7: U1.G20(NDQ7/PC15) U7.44(IO7)
NDQS: U1.F21(NDQS/PC24) U7.35(NC16)
NMI#: U1.F5(NMI#) U13.100(NMI#) ; also on sheet 21
NRB0#: R56.1 U1.J23(NRB0/SDC2_CMD/PC6) U7.7(RB1#)
NRB1#: R54.1 U1.J22(NRB1/SDC2_CLK/PC7) U7.6(RB2#)
NRE#: U1.K22(NRE#/PC5) U7.8(RE#)
NWE#: U1.M23(NWE#/SPI0_MOSI/PC0) U7.18(WE#)
NWP: R55.1 U1.M21(NWP/PC16)
OSC24MI: C20.2 U1.N23(CLK24M_IN) X1.1
OSC24MO: C28.2 U1.N22(CLK24M_OUT) X1.2
PLLDV: C18.2 U1.T16(PLLDV)
PLLVP: C16.2 C17.2 R3.2 U1.P16(PLLVP25)
PLLVREG: C19.2 U1.R15(PLLVREG)
PS2-SCK0: U1.E14(HSCL/UART7_TX/PS2_SCK0/PI20)
PS2-SCK1: U1.C15(PS2_SCK1/TCLKIN0/EINT26/SPI0_CS1/PI14)
PS2-SDA0: U1.E13(HSDA/UART7_RX/PS2_SDA0/PI21)
PS2-SDA1: U1.D15(PS2_SDA1/TCLKIN1/EINT27/SPI1_CS1/PI15)
PWM0: U1.A14(PWM0/PB2)
RESET#: C46.2 U1.C14(RESET#) U13.99(RESET#) ; also on sheet 21
REXT-SATA: U1.V21(REXT_SATA)
RTCVDD: C53.2 C54.2 U1.K8(RTC_VDD) ; also on sheet 21
RTCVDD (page 22 A10-IO): U13.39(RTCVDD)
RXN-SATA: U1.U20(RXM_SATA)
RXP-SATA: U1.U21(RXP_SATA)
SA0: TP5.1(TP) U1.W4(SA0) U5.N3(A0) U6.N3(A0)
SA1: TP6.1(TP) U1.R4(SA1) U5.P7(A1) U6.P7(A1)
SA2: TP7.1(TP) U1.U4(SA2) U5.P3(A2) U6.P3(A2)
SA3: TP8.1(TP) U1.M4(SA3) U5.N2(A3) U6.N2(A3)
SA4: TP9.1(TP) U1.Y4(SA4) U5.P8(A4) U6.P8(A4)
SA5: TP10.1(TP) U1.N4(SA5) U5.P2(A5) U6.P2(A5)
SA6: TP11.1(TP) U1.V4(SA6) U5.R8(A6) U6.R8(A6)
SA7: TP12.1(TP) U1.M3(SA7) U5.R2(A7) U6.R2(A7)
SA8: TP13.1(TP) U1.AA3(SA8) U5.T8(A8) U6.T8(A8)
SA9: TP14.1(TP) U1.P4(SA9) U5.R3(A9) U6.R3(A9)
SA10: TP15.1(TP) U1.L3(SA10) U5.L7(A10) U6.L7(A10)
SA11: TP16.1(TP) U1.W3(SA11) U5.R7(A11) U6.R7(A11)
SA12: TP17.1(TP) U1.P3(SA12) U5.N7(A12) U6.N7(A12)
SA13: TP18.1(TP) U1.Y3(SA13) U5.T3(A13) U6.T3(A13)
SA14: TP19.1(TP) U1.R3(SA14) U5.T7(A14) U6.T7(A14)
SATA-PWR: U1.B19(PWM1/PI3)
SBA0: TP20.1(TP) U1.K3(SBA0) U5.M2(BA0) U6.M2(BA0)
SBA1: TP21.1(TP) U1.L4(SBA1) U5.N8(BA1) U6.N8(BA1)
SBA2: TP22.1(TP) U1.K4(SBA2) U5.M3(BA2) U6.M3(BA2)
SCAS: TP25.1(TP) U1.U3(SCAS) U5.K3(CAS#) U6.K3(CAS#)
SCK: R51.2 U1.V1(SCK)
SCK#: R53.2 U1.V2(SCK#)
SCKE0: TP27.1(TP) U1.N3(SCKE0) U5.K9(CKE) U6.K9(CKE)
SCS0: TP26.1(TP) U1.V3(SCS0) U5.L2(CS#) U6.L2(CS#)
SD0-CLK: U1.L20(SDC0_CLK/UART0_TX/PF2) U9.14(SD_CLK)
SD0-CMD: R67.2 U1.L19(SDC0_CMD/JTAG_DO1/PF3) U9.6(SD_CMD)
SD0-D0: R69.2 U1.M19(SDC0_D0/JTAG_DI1/PF1) U9.19(SD_DAT0)
SD0-D1: R70.2 U1.M20(SDC0_D1/JTAG_MS1/PF0) U9.20(SD_DAT1)
SD0-D2: R71.2 U1.K19(SDC0_D2/JTAG_CK1/PF5) U9.1(SD_DAT2)
SD0-D3: R248.2 U1.K20(SDC0_D3/UART0_RX/PF4) U9.3(SD_DAT3)
SD0-DET#: R68.2 U1.E17(EINT28/SPI1_CS0/UART2_RTS/PI16) U9.22(SD_CD_n)
SD3-CD: U1.E16(EINT29/SPI1_CLK/UART2_CTS/PI17)
SD3-CLK: U1.B18(SDC3_CLK/PI5)
SD3-CMD: U1.A18(SDC3_CMD/PI4)
SD3-D0: U1.A17(SDC3_D0/PI6)
SD3-D1: U1.B17(SDC3_D1/PI7)
SD3-D2: U1.A16(SDC3_D2/PI8)
SD3-D3: U1.B16(SDC3_D3/PI9)
SDQ0: RN8.7(R7) U1.AB4(SDQ0)
SDQ1: RN6.7(R7) U1.AC7(SDQ1)
SDQ2: RN8.6(R6) U1.AC4(SDQ2)
SDQ3: RN6.6(R6) U1.AB8(SDQ3)
SDQ4: RN6.5(R5) U1.AC8(SDQ4)
SDQ5: RN8.5(R5) U1.AB5(SDQ5)
SDQ6: RN6.8(R8) U1.AB7(SDQ6)
SDQ7: RN8.8(R8) U1.AC3(SDQ7)
SDQ8: RN7.7(R7) U1.AB2(SDQ8)
SDQ9: RN5.7(R7) U1.Y1(SDQ9)
SDQ10: RN7.6(R6) U1.AC2(SDQ10)
SDQ11: RN5.6(R6) U1.Y2(SDQ11)
SDQ12: RN5.5(R5) U1.AA1(SDQ12)
SDQ13: RN7.5(R5) U1.AB3(SDQ13)
SDQ14: RN5.8(R8) U1.W2(SDQ14)
SDQ15: RN7.8(R8) U1.AC1(SDQ15)
SDQ16: RN3.7(R7) U1.N1(SDQ16)
SDQ17: RN4.7(R7) U1.T2(SDQ17)
SDQ18: RN3.6(R6) U1.N2(SDQ18)
SDQ19: RN4.6(R6) U1.U1(SDQ19)
SDQ20: RN4.5(R5) U1.U2(SDQ20)
SDQ21: RN3.5(R5) U1.P1(SDQ21)
SDQ22: RN4.8(R8) U1.T1(SDQ22)
SDQ23: RN3.8(R8) U1.M2(SDQ23)
SDQ24: RN2.7(R7) U1.L1(SDQ24)
SDQ25: RN1.7(R7) U1.H1(SDQ25)
SDQ26: RN2.6(R6) U1.L2(SDQ26)
SDQ27: RN1.6(R6) U1.H2(SDQ27)
SDQ28: RN1.5(R5) U1.J1(SDQ28)
SDQ29: RN2.5(R5) U1.M1(SDQ29)
SDQ30: RN1.8(R8) U1.G2(SDQ30)
SDQ31: RN2.8(R8) U1.K2(SDQ31)
SDQM0: R47.2 U1.AC6(SDQM0)
SDQM1: R48.2 U1.W1(SDQM1)
SDQM2: R39.2 U1.R2(SDQM2)
SDQM3: R40.2 U1.G1(SDQM3)
SDQS0: R43.2 U1.AB6(SDQS0)
SDQS0#: R44.2 U1.AC5(SDQS0#)
SDQS1: R45.2 U1.AB1(SDQS1)
SDQS1#: R46.2 U1.AA2(SDQS1#)
SDQS2: R35.2 U1.R1(SDQS2)
SDQS2#: R36.2 U1.P2(SDQS2#)
SDQS3: R37.2 U1.K1(SDQS3)
SDQS3#: R38.2 U1.J2(SDQS3#)
SMC-DET: U1.B1(LCD1_D16/ATAD12/KP_IN6/SMC_DET/EINT16/CSI1_D16/PH16)
SMC-RST: U1.A2(LCD1_D13/ATAD9/PS2_SDA1/SMC_RST/EINT13/CSI1_D13/PH13)
SMC-SDA: U1.D1(LCD1_D19/ATAD15/KP_OUT1/SMC_SDA/EINT19/CSI1_D19/PH19)
SMC-SLK: U1.C2(LCD1_D18/ATAD14/KP_OUT0/SMC_SLK/EINT18/CSI1_D18/PH18)
SMC-VCCEN: U1.C1(LCD1_D17/ATAD13/KP_IN7/SMC_VCCEN/EINT17/CSI1_D17/PH17)
SODT0: R41.2 U1.AA5(ODT0)
SPDIF-DO: U1.B11(SPI2_CS1/SPDIF_DO/PB13) ; also on sheet 16
SPI0-CLK: J3.2 R58.1 U1.D17(SPI0_CLK/UART5_RX/EINT23/PI11)
SPI0-CS0: J3.1 R57.1 U1.C17(SPI0_CS0/UART5_TX/EINT22/PI10)
SPI0-MISO: R60.1 U1.D16(SPI0_MISO/UART6_RX/EINT25/PI13)
SPI0-MOSI: R59.1 U1.C16(SPI0_MOSI/UART6_TX/EINT24/PI12)
SPI0-NOR-CLK: R58.2 U8.6(CLK)
SPI0-NOR-CS0: R57.2 R62.2 U8.1(CS#)
SPI0-NOR-MISO: R60.2 U8.2(MISO)
SPI0-NOR-MOSI: R59.2 U8.5(MOSI)
SPI0-NOR-WP#: R61.2 U8.3(WP#)
SPI0_CS1: U13.44(SPI0-CS1)
SPI2-CLK: U1.K21(NCE5/SPI2_CLK/PC20)
SPI2-CS0: U1.L21(NCE4/SPI2_CS0/PC19)
SPI2-MISO: U1.J20(NCE7/SPI2_MISO/PC22)
SPI2-MOSI: U1.J21(NCE6/SPI2_MOSI/PC21)
SRAS: TP24.1(TP) U1.T4(SRAS) U5.J3(RAS#) U6.J3(RAS#)
SRST: R42.2 U1.AA6(SRST)
SVREF0: C130.2 C132.1 R32.1 R34.2 U1.AA8(SVREF3) U1.H3(SVREF0) U1.H4(SVREF1) U1.Y5(SVREF2)
SWE: TP23.1(TP) U1.T3(SWE) U5.L3(WE) U6.L3(WE)
SZQ: R1.2 U1.AA7(SZQ)
TV-OUT0: U1.AC16(TVOUT0)
TV-OUT1: U1.AB16(TVOUT1)
TV-OUT2: U1.AC17(TVOUT2)
TV-OUT3: U1.AB17(TVOUT3) ; also on sheet 18
TVDACVCC: C71.2 C72.2 R9.2 U1.W15(VCC33_TVOUT)
TVIN0: U1.AC18(TVIN0)
TVIN1: U1.AB18(TVIN1)
TVIN2: U1.AA17(TVIN2)
TVIN3: U1.Y17(TVIN3)
TWI0-SCK: R97.1 U1.A15(TWI0_SCK/PB0) U13.102(TWI0-SCK) U25.3(SCK) ; also on sheet 21
TWI0-SDA: R102.1 U1.B15(TWI0_SDA/PB1) U13.101(TWI0-SDA) U25.2(SDA) ; also on sheet 21
TWI1-SCK: R14.2 R99.1 U1.A8(TWI1_SCK/PB18) U13.96(TWI1-SCK) ; also on sheet 13
TWI1-SDA: R12.2 R98.1 U1.B8(TWI1_SDA/PB19) U13.97(TWI1-SDA) ; also on sheet 13
TWI2-SCK: R15.2 U1.C8(TWI2_SCK/PB20)
TWI2-SCK (page 22 A10-IO): R101.1 U13.94(TWI2-SCK)
TWI2-SDA: R13.2 U1.C7(TWI2_SDA/PB21)
TWI2-SDA (page 22 A10-IO): R100.1 U13.95(TWI2-SDA)
TXN-SATA: U1.T21(TXM_SATA)
TXP-SATA: U1.T20(TXP_SATA)
UART0-RX: U1.B7(UART0_RX/IR1_RX/PB23) ; also on sheet 13
UART0-TX: U1.A7(UART0_TX/IR1_TX/PB22) ; also on sheet 13
UBOOT: U1.W8(UBOOT_SEL) ; also on sheet 14
ULVDD: C65.2 C66.2 R7.2 U1.K16(ULVDD)
USB0-DRV: U13.103(USB0-DRV)
USB-DRV: R254.2 U27.4(EN)
USBVBUS: C142.2 C143.2 P1.1(VBUS) R65.1 U10.1(OUT)
UVCC: C67.2 C68.2 R8.2 U1.L15(UVCC_T) U1.L16(UVCC_C)
VMIC: U1.AA21(VMIC)
VPS: NSR2.2 NSR3.1 U7.38(VSS3)
VRA1: C48.2 U1.W20(VRA1)
VRA2: C47.2 C49.2 R5.2 U1.V20(VRA2)
VRN-TVIN: C78.2 U1.Y16(VRN_TVIN)
VRP: C43.2 C45.2 U1.W21(VRP)
VRP-TVIN: C77.2 U1.AA16(VRP_TVIN)
X1: C50.2 U1.Y22(XP_TP) U13.146(X1)
X2: C56.2 U1.AA22(XN_TP) U13.144(X2)
Y1: C51.2 U1.Y23(YP_TP) U13.147(Y1)
Y2: C57.2 U1.AA23(YN_TP) U13.145(Y2)
N16789411: FB1.2 P1.6(SHIELD1) P1.7(SHIELD2) P1.8(SHIELD3) P1.9(SHIELD4)
N18993908: C138.2 R61.1 R62.1 R63.2 U8.7(HOLD#) U8.8(VCC)
N20610439: R64.1 U10.3(ISET)
N22027658: P10.5(SHLD0) P10.6(SHLD1) P10.7(SHLD2) P10.8(SHLD3) ZD14.2
N22027669: P7.1(VBUS) P8.1(VBUS) P9.1(VBUS) P10.1(VBUS) U27.6(OUT0) U27.7(OUT1)
N22027744: P8.5(SHLD0) P8.6(SHLD1) P8.7(SHLD2) P8.8(SHLD3) ZD12.2
N22027758: P9.5(SHLD0) P9.6(SHLD1) P9.7(SHLD2) P9.8(SHLD3) ZD13.2
N22027791: P7.5(SHLD0) P7.6(SHLD1) P7.7(SHLD2) P7.8(SHLD3) ZD11.2
N22027810: C236.2 U11.23(V5)
N22027861: R253.1 U27.5(FLG)
N22027948: R251.1 U11.4(RREF)
N22027954: C232.1 R249.1 U11.6(X1) X4.1
N22027956: C233.1 R250.1 U11.13(RESET#)
N22027962: C231.1 R249.2 U11.7(X2) X4.2
N22028006: R252.2 U11.17(PSELF)
N22031825: R131.2 R132.1 U13.143(LRADC0)
N22031989: K10.2 R132.2 R133.1
N22032208: K12.2 U13.2(UBOOT)
N22032620: K11.2 R133.2
N26710850: R50.2 U6.L8(ZQ)
N26735772: R49.2 U5.L8(ZQ)

Not connected (* = marked no-connect by the designer): U1 AA4(SCS1)* AB22(LRADC1)* AC22(MIC1OUTP)* AC23(MIC1OUTN)* J3(ODT1)* J4(SCKE1)* N8(ADBG)* P8(SDBG0)* P19(CLKM_SATA)* R8(SDBG1)* R16(PLLREGIO)* R19(CLKP_SATA)* T15(PLLTEST)*; U5 J1(NC#1) J9(NC#3) L1(NC#2) L9(NC#4) M7(A15)*; U6 J1(NC#1) J9(NC#3) L1(NC#2) L9(NC#4) M7(A15)*; U7 3(NC3)* 4(RB4#)* 5(RB3#)* 11(NC4)* 14(CE3#)* 15(CE4#)* 20(NC5)* 21(NC6)* 22(NC7)* 26(NC11)* 27(NC12)* 28(NC13)* 33(NC14)* 40(NC18)* 45(NC19)* 46(NC20)* 47(NC21)*; U9 21(SD_WP); U11 14(TEST)* 18(PGANG)* 19(OVCUR2#)* 20(PWREN2)* 21(OVCUR1#)* 22(PWREN1)*; U13 1(NC0) 5(ESRXP) 6(ESRXM) 7(ESTXM) 8(ESTXP) 9(HTXCN) 10(HTXCP) 11(HTX0N) 12(HTX0P) 13(HTX1N) 14(HTX1P) 15(HTX2N) 16(HTX2P) 17(HSDA) 18(HSCL) 19(HHPD) 20(HCEC) 27(SD0-D1) 28(SD0-D0) 29(SD0-CLK) 30(SD0-DET#) 31(SD0-CMD) 32(SD0-D3) 33(SD0-D2) 45(IR-RX) 46(BT-UART-RTS) 47(BT-UART-CTS) 48(BT-UART-TX) 49(BT-UART-RX) 55(EPHY-RST#) 68(VCC-3V3A) 69(VCC-3V3B) 70(UART7-RX) 71(UART7-TX) 72(LCD0-SCK) 73(LCD0-SDA) 74(SPDIF) 104(PWM0) 134(NC1) 135(VGA-G) 136(VGA-B) 137(VGA-R) 138(CVBS) 139(TVIN0) 140(TVIN1) 141(TVIN2) 142(TVIN3); U25 4(NC0) 5(NC1) 6(NC2) 7(NC3)

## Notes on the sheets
sheet 2
- BLOCK
- YPbPr OUT
- TV IN X 4
- PIO JACK
- CVBS OUT
- UART0
- RS232
- VGA OUT
- USB0 OTG
- SMART CARD
- For debug
- TS1
- UART2
- RS232
- HDMI/1080P
- TS0
- USB1 HOST
- EMAC
- JTAG
- LCD/LVDS
- USB2 HOST
- FILTER
- CIS1
- BUFFER
- CPU
- A10
- BGA441
- LINEIN
- SPI NOR
- IR
- IIS JACK
- DDR3
- DDR3
- NANDFLASH
- MIC *2
- KEY
- SPDIF OUT
- SD0/MMS
- FOR BOOT
- WIFI(SD3)
- SPDIF IN
- HEADPHONE
- PS2-1
- SATA
- 256MB X 2 DDR3 (512MB)
- PS2-0
sheet 3
- PIO ASSIGNMENT
- Pin
  Group
- Pin
  Group
- Pin
  Group
- Pin
  Group
- Pin
  Group
- Pin Name
- Define
- Function
- Pin Name
- Define
- Function
- Pin Name
- Define
- Function
- Pin Name
- Define
- Function
- Pin Name
- Define
- Function
- PI14
- PS2-SCK1
- PA0
- ERXD3
- PC0
- NWE#
- PD18
- LCD0_D18
- PH0
- EINT0
- CSI1_D0
- PS2-1
- PA1
- ERXD2
- PC1
- PD19
- LCD0_D19
- PH1
- EINT1
- PI15
- PS2-SDA1
- NALE
- CSI1_D1
- PA2
- ERXD1
- PC2
- NCLE
- PD20
- LCD0_D20
- PH2
- EINT2
- CSI1_D2
- PI16
- UART2-RTS
- SD0-DET#
- PI(22)
- PI17
- PA3
- ERXD0
- PC3
- NCE1
- PD21
- LCD0_D21
- PH3
- EINT3
- CSI1_D3
- UART2-CTS
- SD3-CD
- PA4
- ETXD3
- PC4
- PD22
- LCD0_D22
- PH4
- EINT4
- PI18
- NCE0
- PD(28)
- LCD
- CSI1_D4
- UART2-TX
- DetVBUS0
- PA5
- ETXD2
- PC5
- NRE#
- PD23
- LCD0_D22
- PH5
- EINT5
- PI19
- UART2-RX
- CSI1_D5
- PI20
- PS2-SCK0
- ID0
- PA6
- ETXD1
- PC6
- NRB0
- PD24
- LCD0_CLK
- PH6
- MS-BS
- PS2-0
- PA7
- ETXD0
- PC7
- PD25
- LCD0_DE
- PI21
- PS2-SDA0
- PA(18)
- EMAC
- NRB1
- PH7
- MS-CLK
- PA8
- ERXCK
- PC8
- NDQ0
- PD26
- LCD0_HSYNC
- PH8
- MS-D0
- MS
- PA9
- ERXERR
- PC9
- NDQ1
- PD27
- LCD0_VSYNC
- PH9
- MS-D1
- PA10
- ERXDV
- PC10
- NDQ2
- PE0
- CSI0_PCLK
- PH10
- MS-D2
- PA11
- EMDC
- PC11
- NDQ3
- PE1
- CSI0_MCLK
- PH11
- MS-D3
- PA12
- EMDIO
- PC12
- NDQ4
- PE2
- CSI0_HSYNC
- PH12
- EINT12
- DrvVBUS0
- PC(25)
- NAND
- PH(28)
- PA13
- ETXEN
- PC13
- NDQ5
- PE3
- CSI0_VSYNC
- PH13
- EINT13
- SMC-RST
- PA14
- ETXCK
- PC14
- PE4
- CSI0_D0
- PH14
- DrvVBUS2
- NDQ6
- EINT14
- PA15
- ECRS
- PC15
- NDQ7
- PE(12)
- PE5
- CSI0_D1
- TS0
- PH15
- EINT15
- LCD-PIO0
- PA16
- ECOL
- PC16
- NWP
- PE6
- CSI0_D2
- PH16
- EINT16
- SMC-DET
- PA17
- ETXERR
- SMC-VCCEN
- PC17
- NCE2
- PE7
- CSI0_D3
- PH17
- EINT17
- PB0
- TWI0_SCK
- PC18
- NCE3
- PE8
- CSI0_D4
- PH18
- EINT18
- SMC-SLK
- TWI0
- PB1
- TWI0_SDA
- PC19
- SPI2-CS0
- PE9
- CSI0_D5
- PH19
- EINT19
- SMC-SDA
- CSI0_D6
- PB2
- PWM0
- PWM
- PC20
- SPI2-CLK
- PE10
- PH20
- EINT20
- CSI0-PIO1
- PB3
- MUTE
- PC21
- SPI2
- PE11
- CSI0_D7
- PH21
- EINT21
- CSI1-PIO0
- SPI2-MOSI
- PB4
- IR0_RX
- IR
- PC22
- SPI2-MISO
- PF0
- SDC0_D1
- PH22
- SDC1_CMD
- CSI1-PIO1
- SDC1_CLK
- PB5
- I2S_MCLK
- PC23
- LCD-PWR
- PF1
- SDC0_D0
- PH23
- DrvVBUS1
- PB6
- I2S_BCLK
- PC24
- NDQS
- PF2
- SDC0_CLK
- PH24
- SDC1_D0
- CSI1-PCLK
- PB7
- I2S_LRCK
- PD0
- LCD0_D0
- PF(6)
- PF3
- SDC0_CMD
- SDC0
- PH25
- SDC1_D1
- CSI1-MCLK
- PB8
- I2S_DO0
- PD1
- LCD0_D1
- PF4
- SDC0_D3
- PH26
- CSI1-HSYNC
- PB9
- I2S_DO1
- IIS
- LCD0_D2
- CSI1-VSYNC
- PD2
- PF5
- SDC0_D2
- PH27
- PB10
- I2S_DO2
- PD3
- LCD0_D3
- PG0
- CSI1_PCLK
- PI0
- GPS_CLK
- LCD-PIO0
- PB(24)
- PB11
- I2S_DO3
- PD4
- LCD0_D4
- PG1
- CSI1_MLCK
- PI1
- GPS_SIGN
- LCD-PIO1
- PB12
- LCD0_D5
- CSI1_HSYNC
- GPS_MAG
- I2S_DI
- PD5
- PG2
- PI2
- LCD-PIO2
- PB13
- SPDIF_DO
- SPDIF
- PD6
- LCD0_D6
- PG3
- CSI1_VSYNC
- PI3
- SATA-PWR
- PB14
- JTAG_MS0
- PD7
- LCD0_D7
- PG4
- CSI1_D0
- PI4
- SDC3_CMD
- PB15
- JTAG_CK0
- PD(28)
- LCD
- SDC3_CLK
- PD8
- LCD0_D8
- PG5
- CSI1_D1
- PI5
- PB16
- JTAG_DO0
- JTAG
- PD9
- LCD0_D9
- PG(12)
- PG6
- CSI1_D2
- TS1
- PI(22)
- PI6
- SDC3_D0
- CARD3
- PB17
- JTAG_DI0
- PD10
- LCD0_D10
- PI7
- SDC3_D1
- WIFI
- TWI1_SCK
- PG7
- CSI1_D3
- SDC3_D2
- PB18
- PD11
- LCD0_D11
- PI8
- PB19
- TWI1_SDA
- TWI1
- PD12
- LCD0_D12
- PI9
- SDC3_D3
- PG8
- CSI1_D4
- PB20
- TWI2_SCK
- PD13
- LCD0_D13
- PI10
- SPI0_CS0
- TWI2
- PG9
- CSI1_D5
- SPI0_CLK
- PB21
- TWI2_SDA
- PD14
- LCD0_D14
- PI11
- LCD0_D15
- PI12
- SPI0_MOSI
- SPI0
- PB22
- UART0_TX
- PD15
- PG10
- CSI1_D6
- UART0
- PD16
- LCD0_D16
- PI13
- SPI0_MISO
- PB23
- UART0_RX
- PG11
- CSI1_D7
- PD17
- LCD0_D17
sheet 4
- POWER TREE
- 5V@2A
- MP1482
- DC/DC2-1.25V-1.6A
- for CPU
- ACIN(12V)2A
- Battery
  charger
  /detect
- DC/DC3-1.2V-1.2A
- INTERLOGIC/USB/DLL
- AXP209
- LDO1-1.3V-30mA
- RTC-VDD
- Switch
  NDS9435A
- PWR MOS
- LDO2-3.00V-200mA
- AVCC
- LDO3-2.80V-200mA
- CSI0-IO
- USB HOST(5V)
- LDO4-1.80-3.3V-50mA
- CSI1-IO
- MP1483
- 5V@2A
- SATA-12V
- SATA-5V
- SY8021L
- RT9293B
- IT6400FB
- 2V5@200mA
- 1V5@1A
- 3V3@1A
- DDR3
- Peripheral
- LCD
  BACKLIGHT
- TV IN
- SYSTEM
sheet 5
- CPU1
sheet 6
- CPU2
sheet 7
- DRAM-DLL
- PLL-NAND
- CRYSTAL
- INTERLOGIC
- AUDIO-SYS-TP
- PIO-INTFACE
- HPVCCIN
- USB-CPU
- CSI-TV
- TWI-PULLUP
- HDMI
sheet 8
- DDR3
- 另外增加放在DARM边上
sheet 9
- NAND Flash
- (1) 接1片单片选Nand 时，NSR4、NSR5断开
  (2) 接1片双片选Nand 时，连接NSR4，断开NSR5
  (3) 接1片四片选Nand 时，连接NSR5，断开NSR4
  (4) 接2片单片选或接2片双片选Nand时，连接NSR5，断开NSR4
  (5) 接Intel、Toshiba、Samsung 2xnm TSOP Nand时， NSR2连接，NSR3断开；其它的NSR2断开，NSR3连接
- SPI Nor Flash
- 当不使用NOR时，作为UART5使用
sheet 10
- USB
- SDMMC & MS
- CARD0
- USB
  Host
- 靠近主控IC摆放
